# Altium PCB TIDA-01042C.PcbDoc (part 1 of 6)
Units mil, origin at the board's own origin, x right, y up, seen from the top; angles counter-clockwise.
Board outline 8300 x 7100 mil, 8 copper layers (Top Layer, Signal Layer 1, Signal Layer 2, Signal Layer 3, Signal Layer 4, Signal Layer 5, Signal Layer 6, Bottom Layer), stack 59.2 mil thick; 551 components, 303 nets, 1611 pads, 2322 vias.
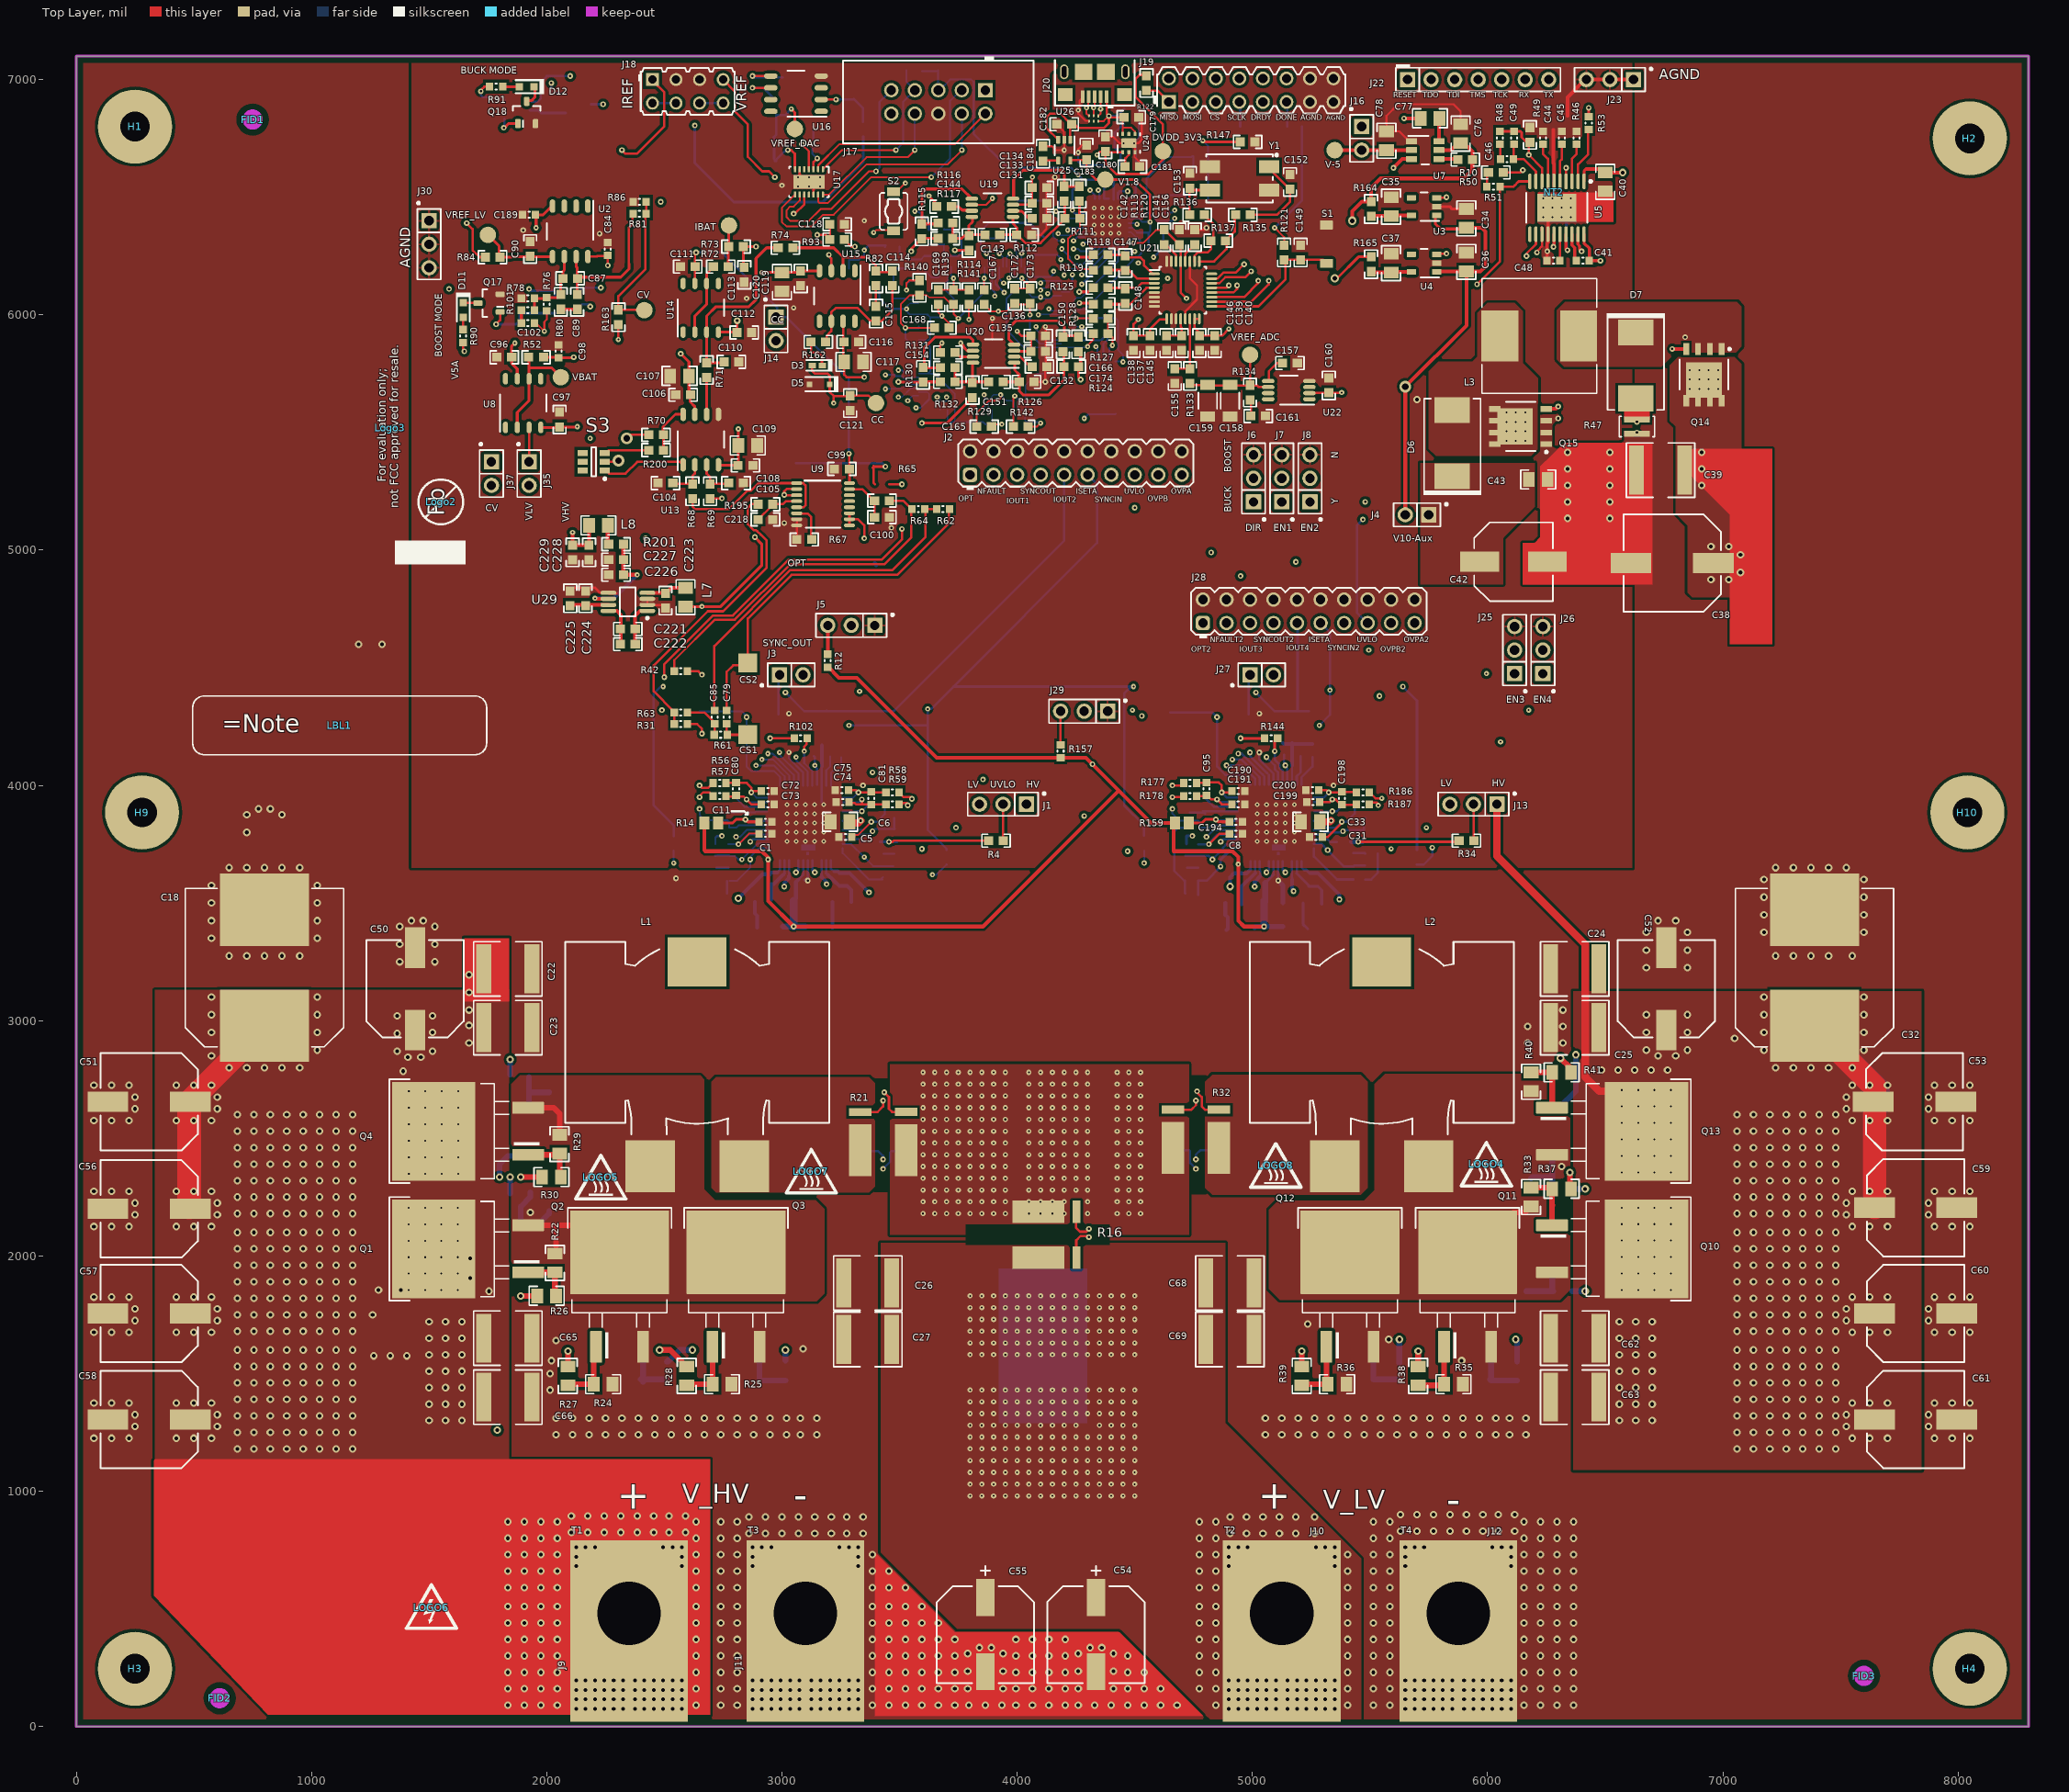
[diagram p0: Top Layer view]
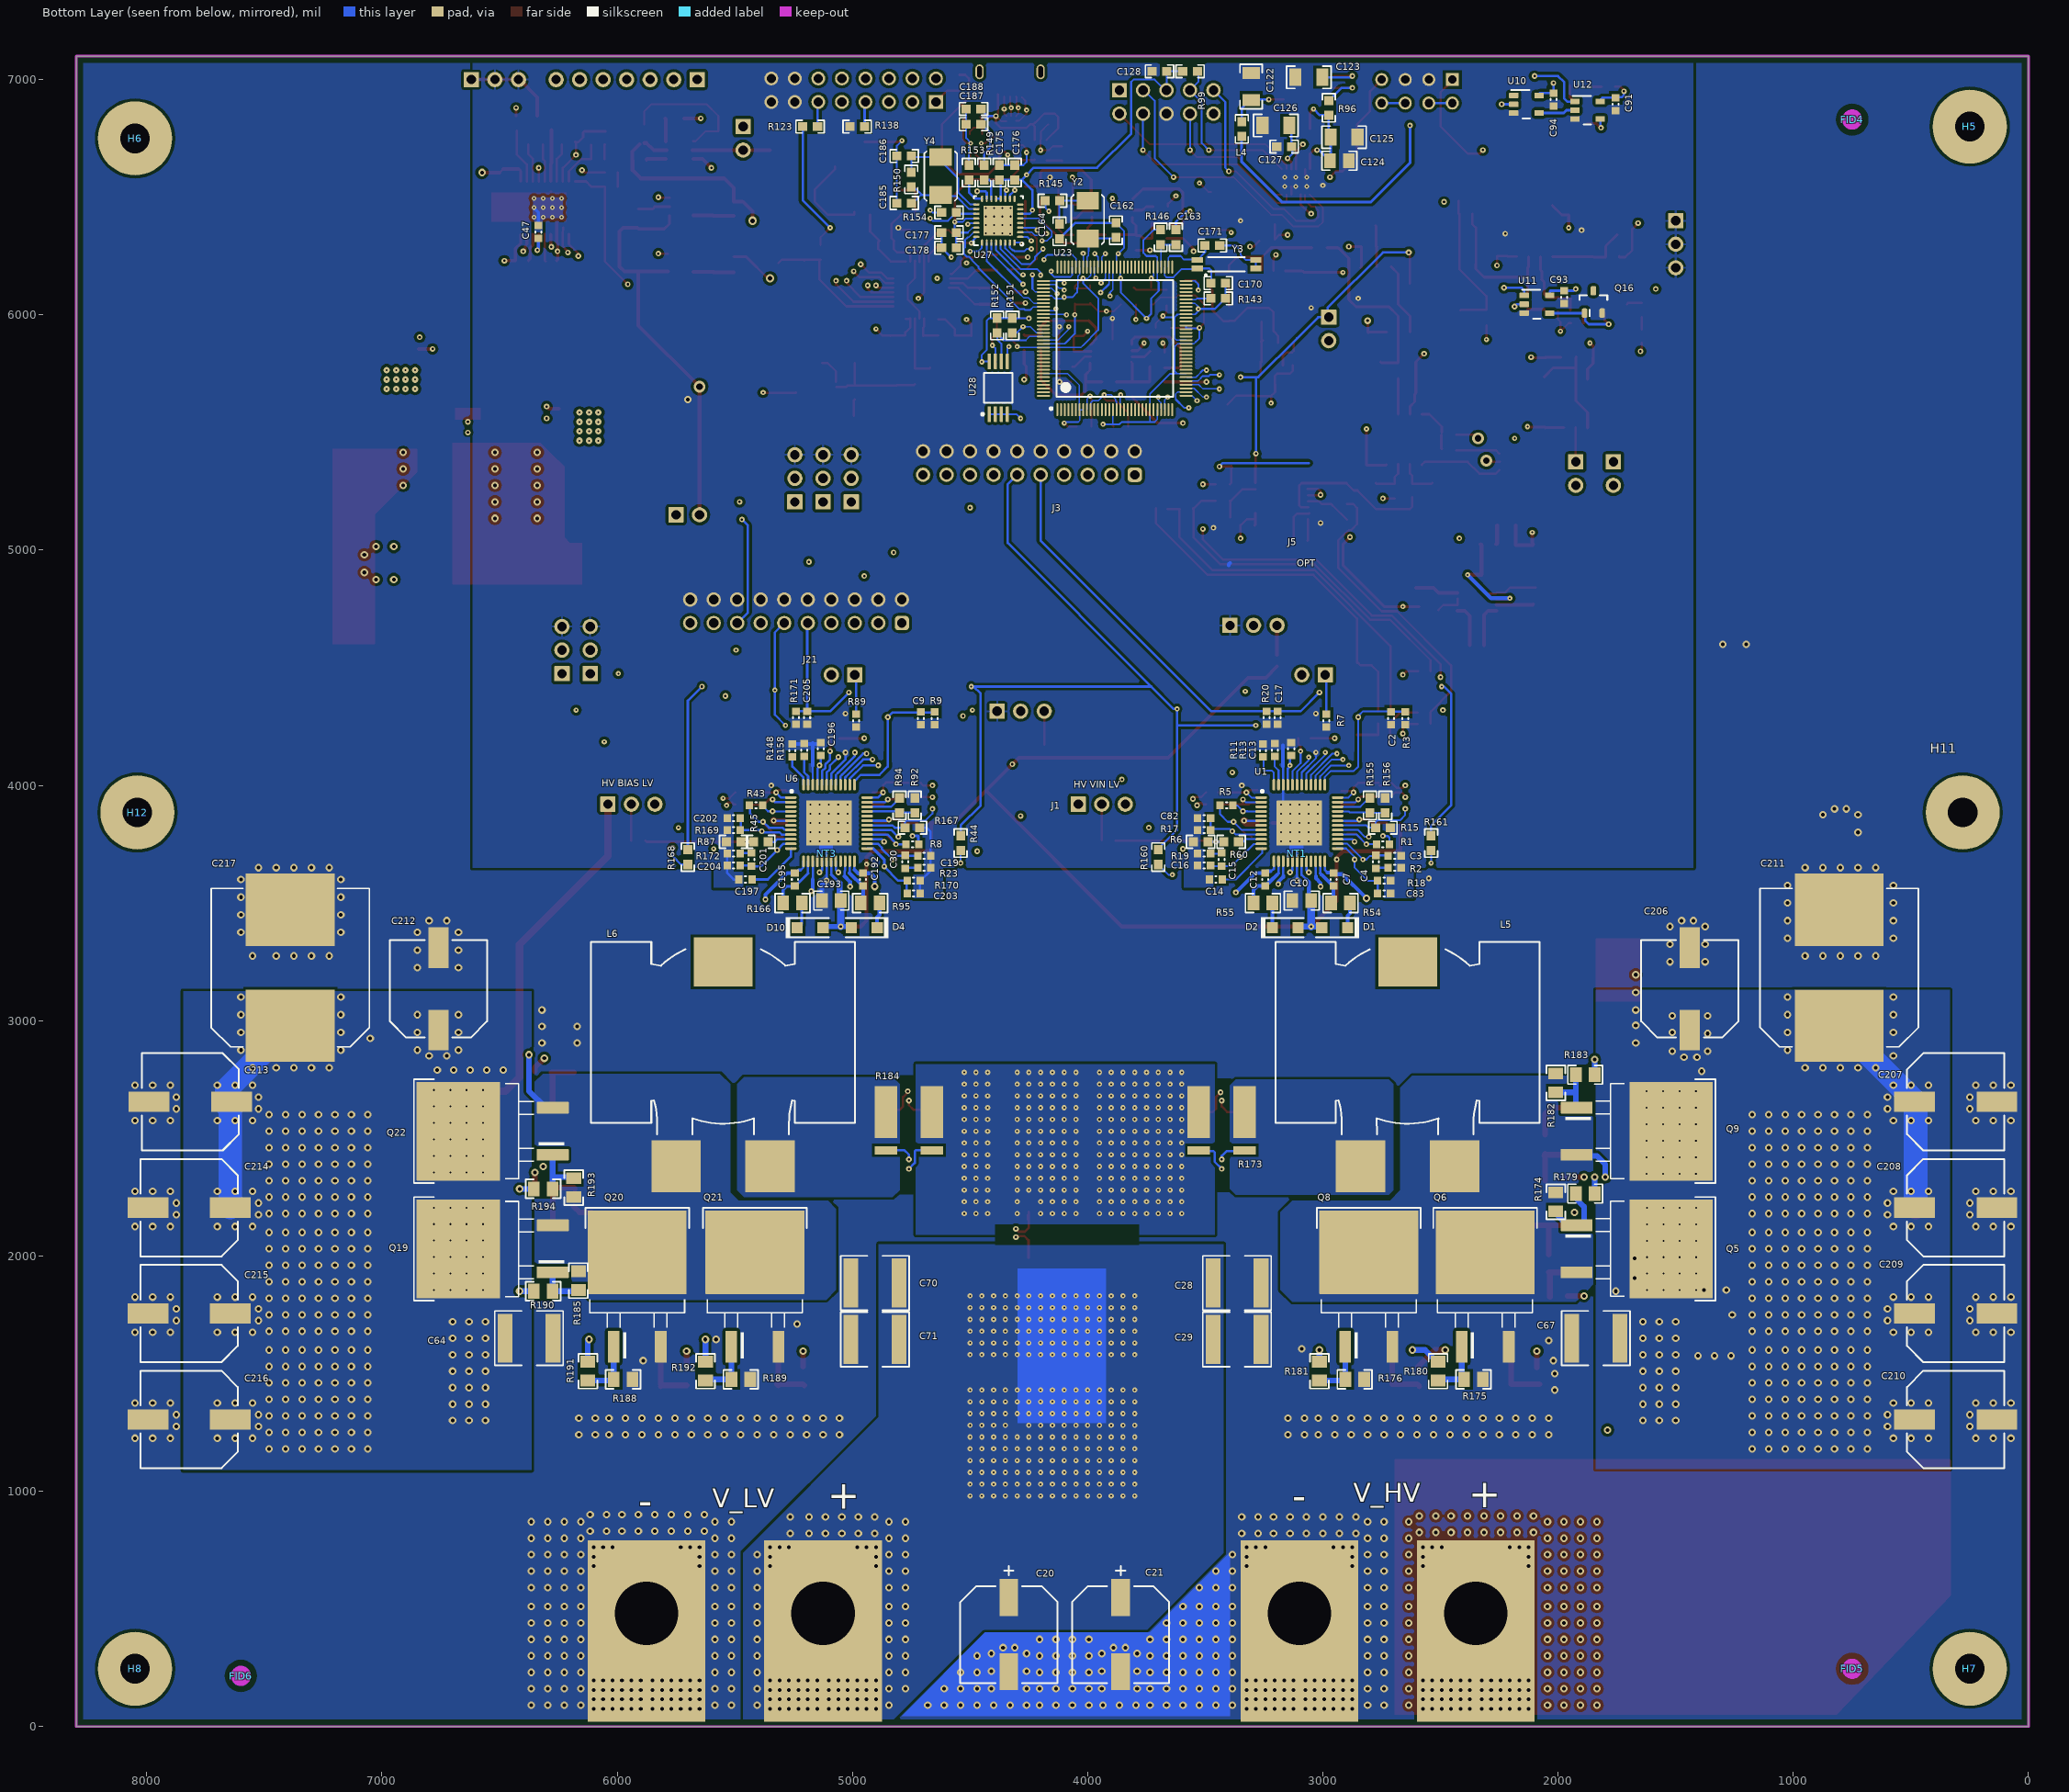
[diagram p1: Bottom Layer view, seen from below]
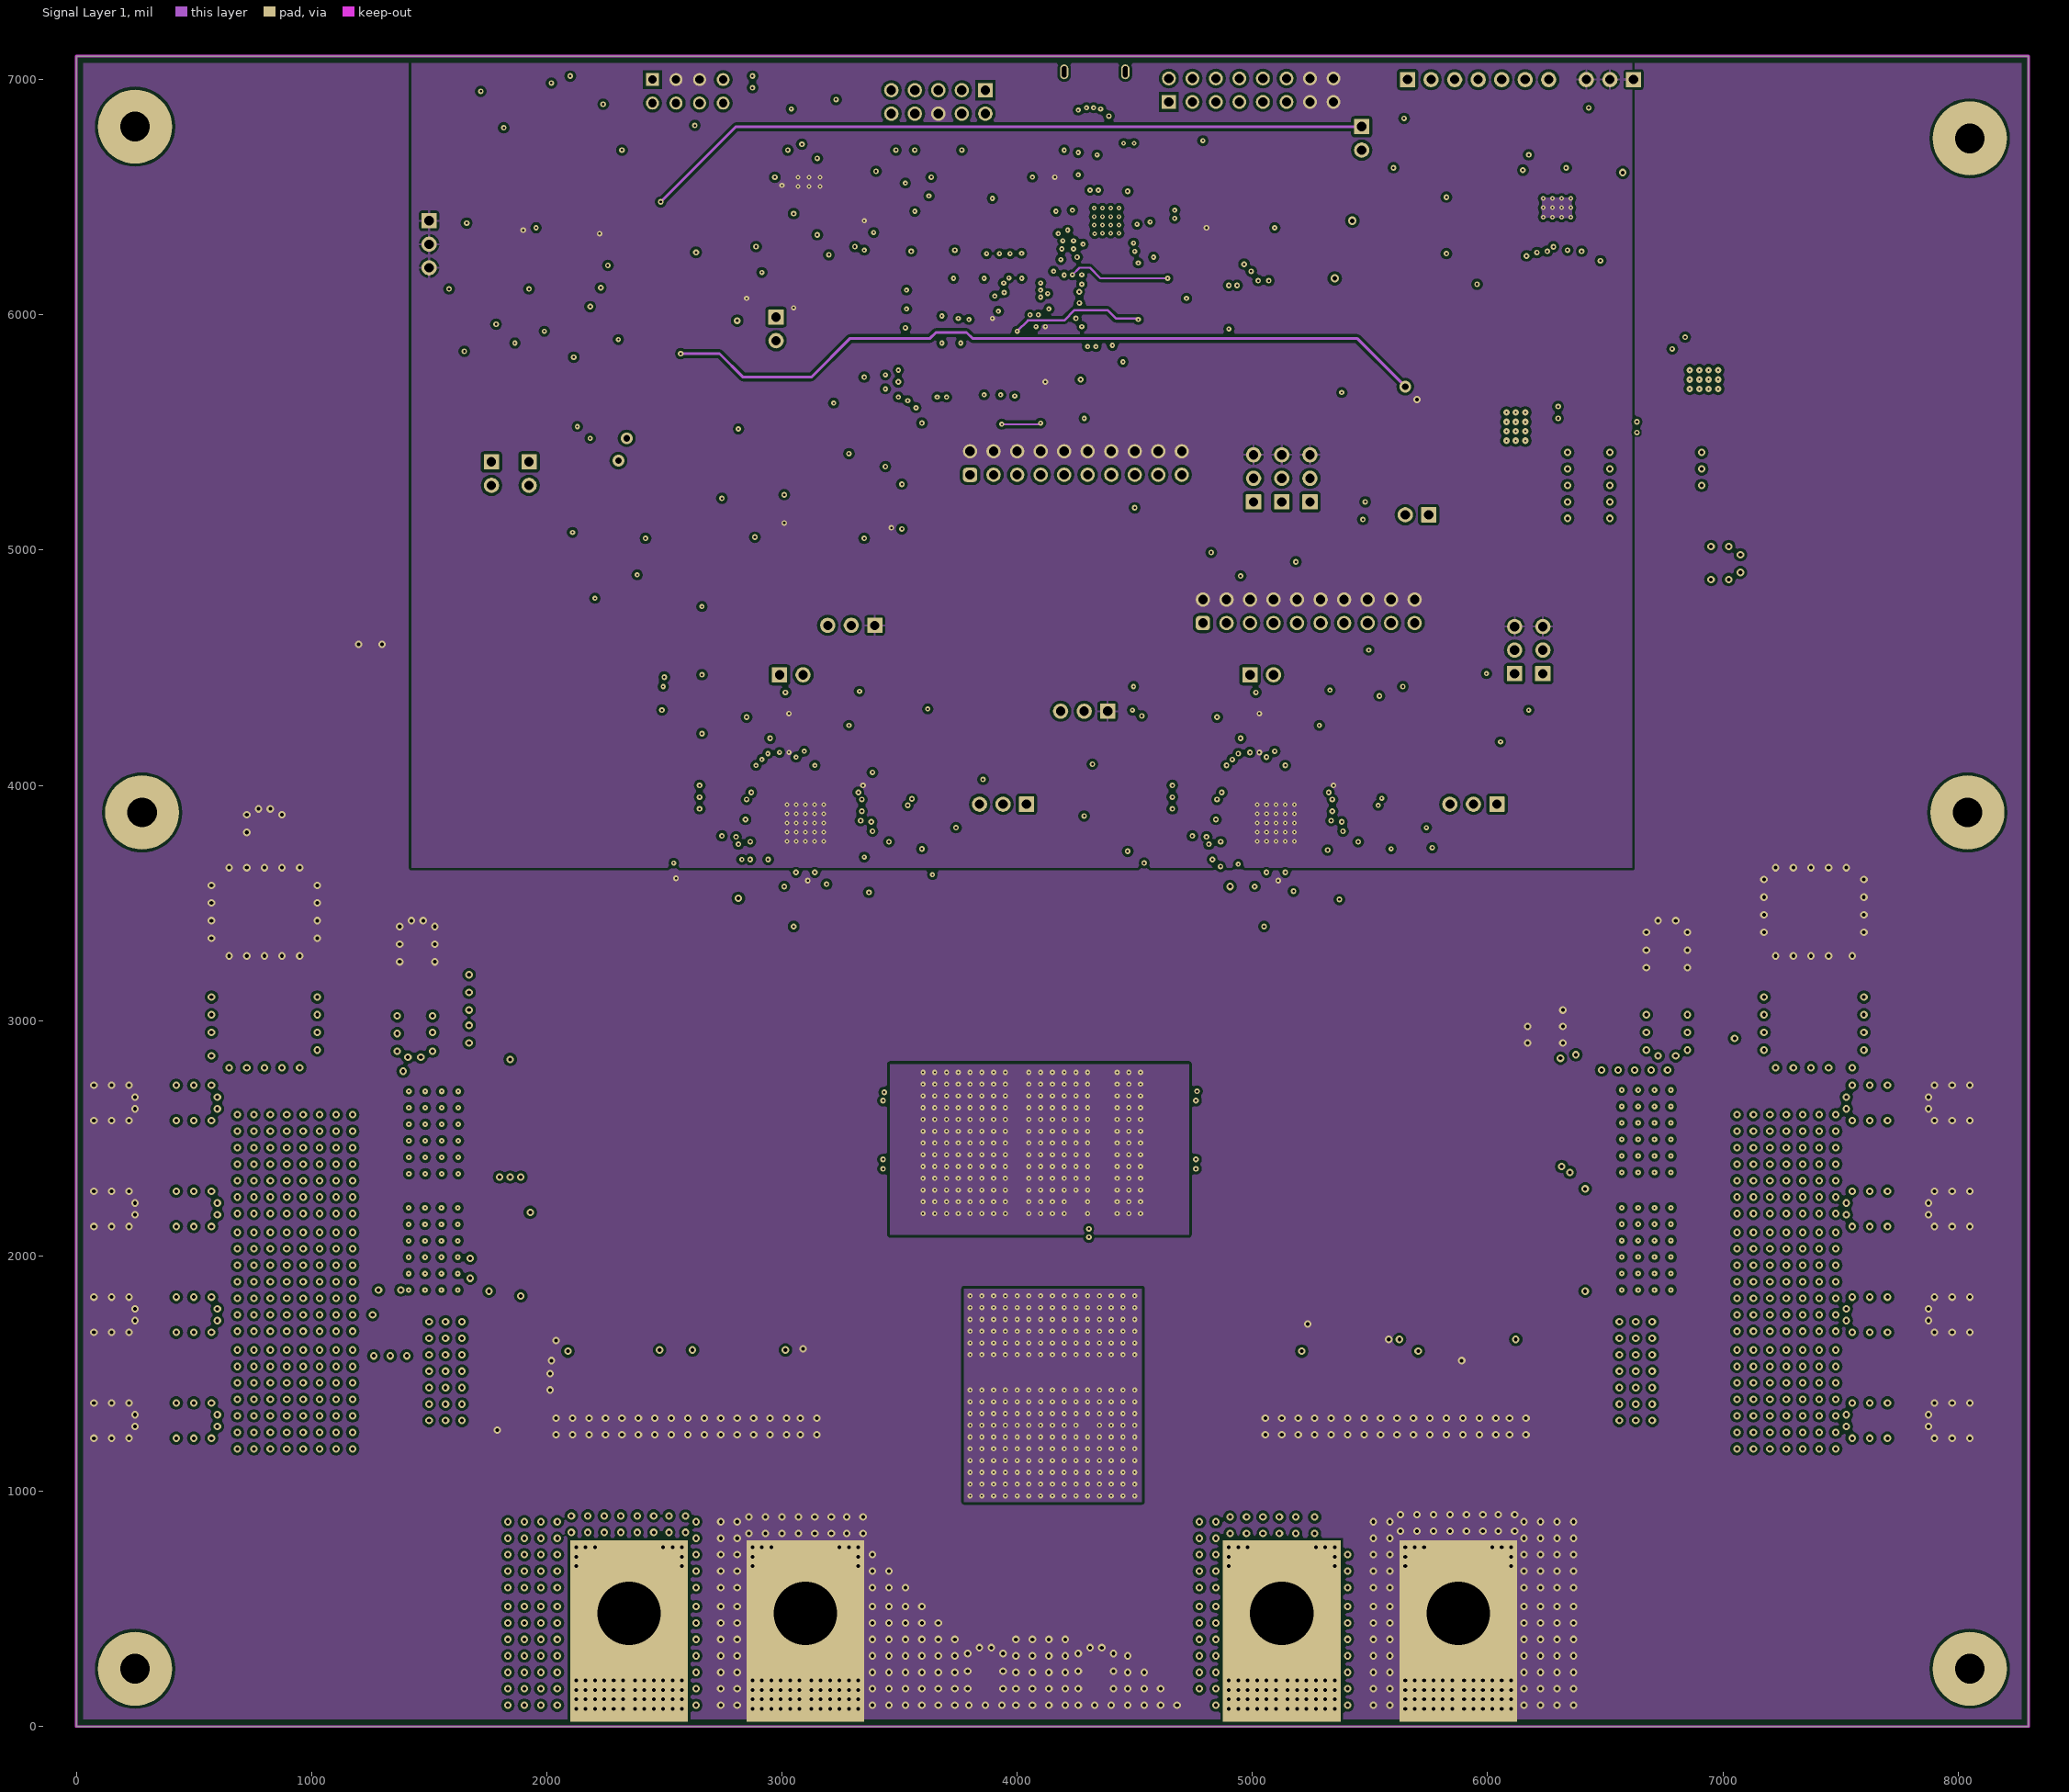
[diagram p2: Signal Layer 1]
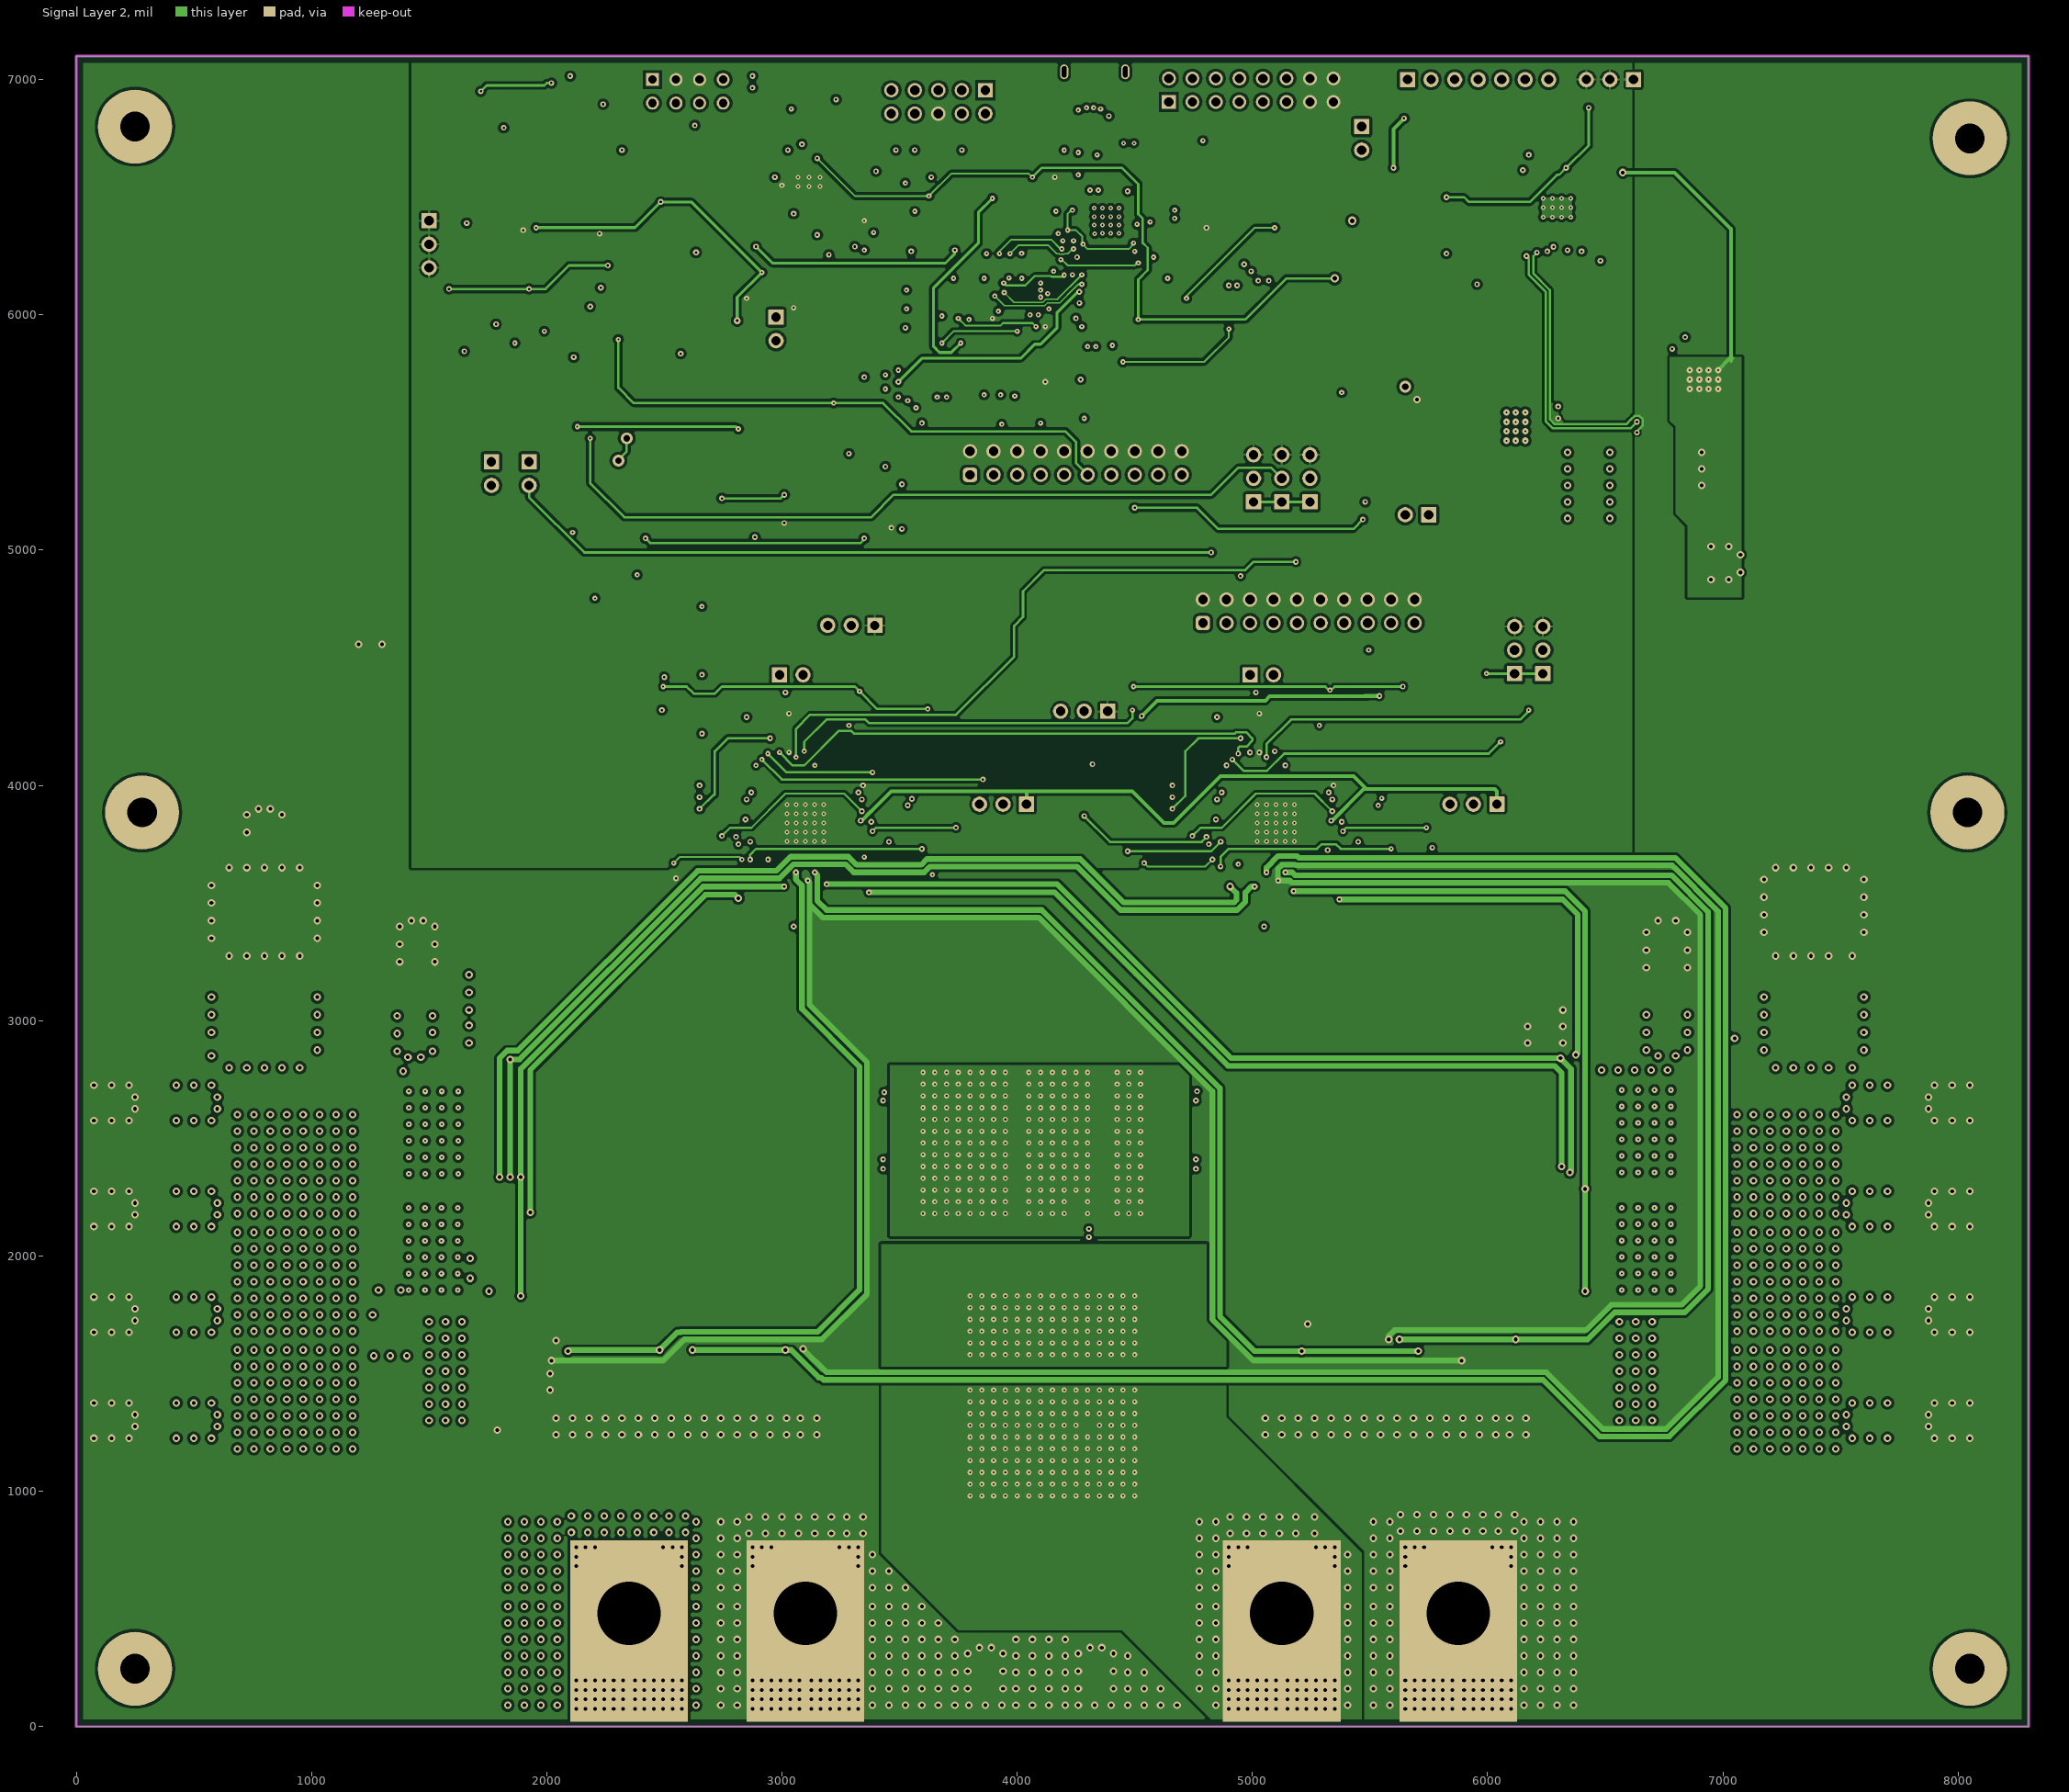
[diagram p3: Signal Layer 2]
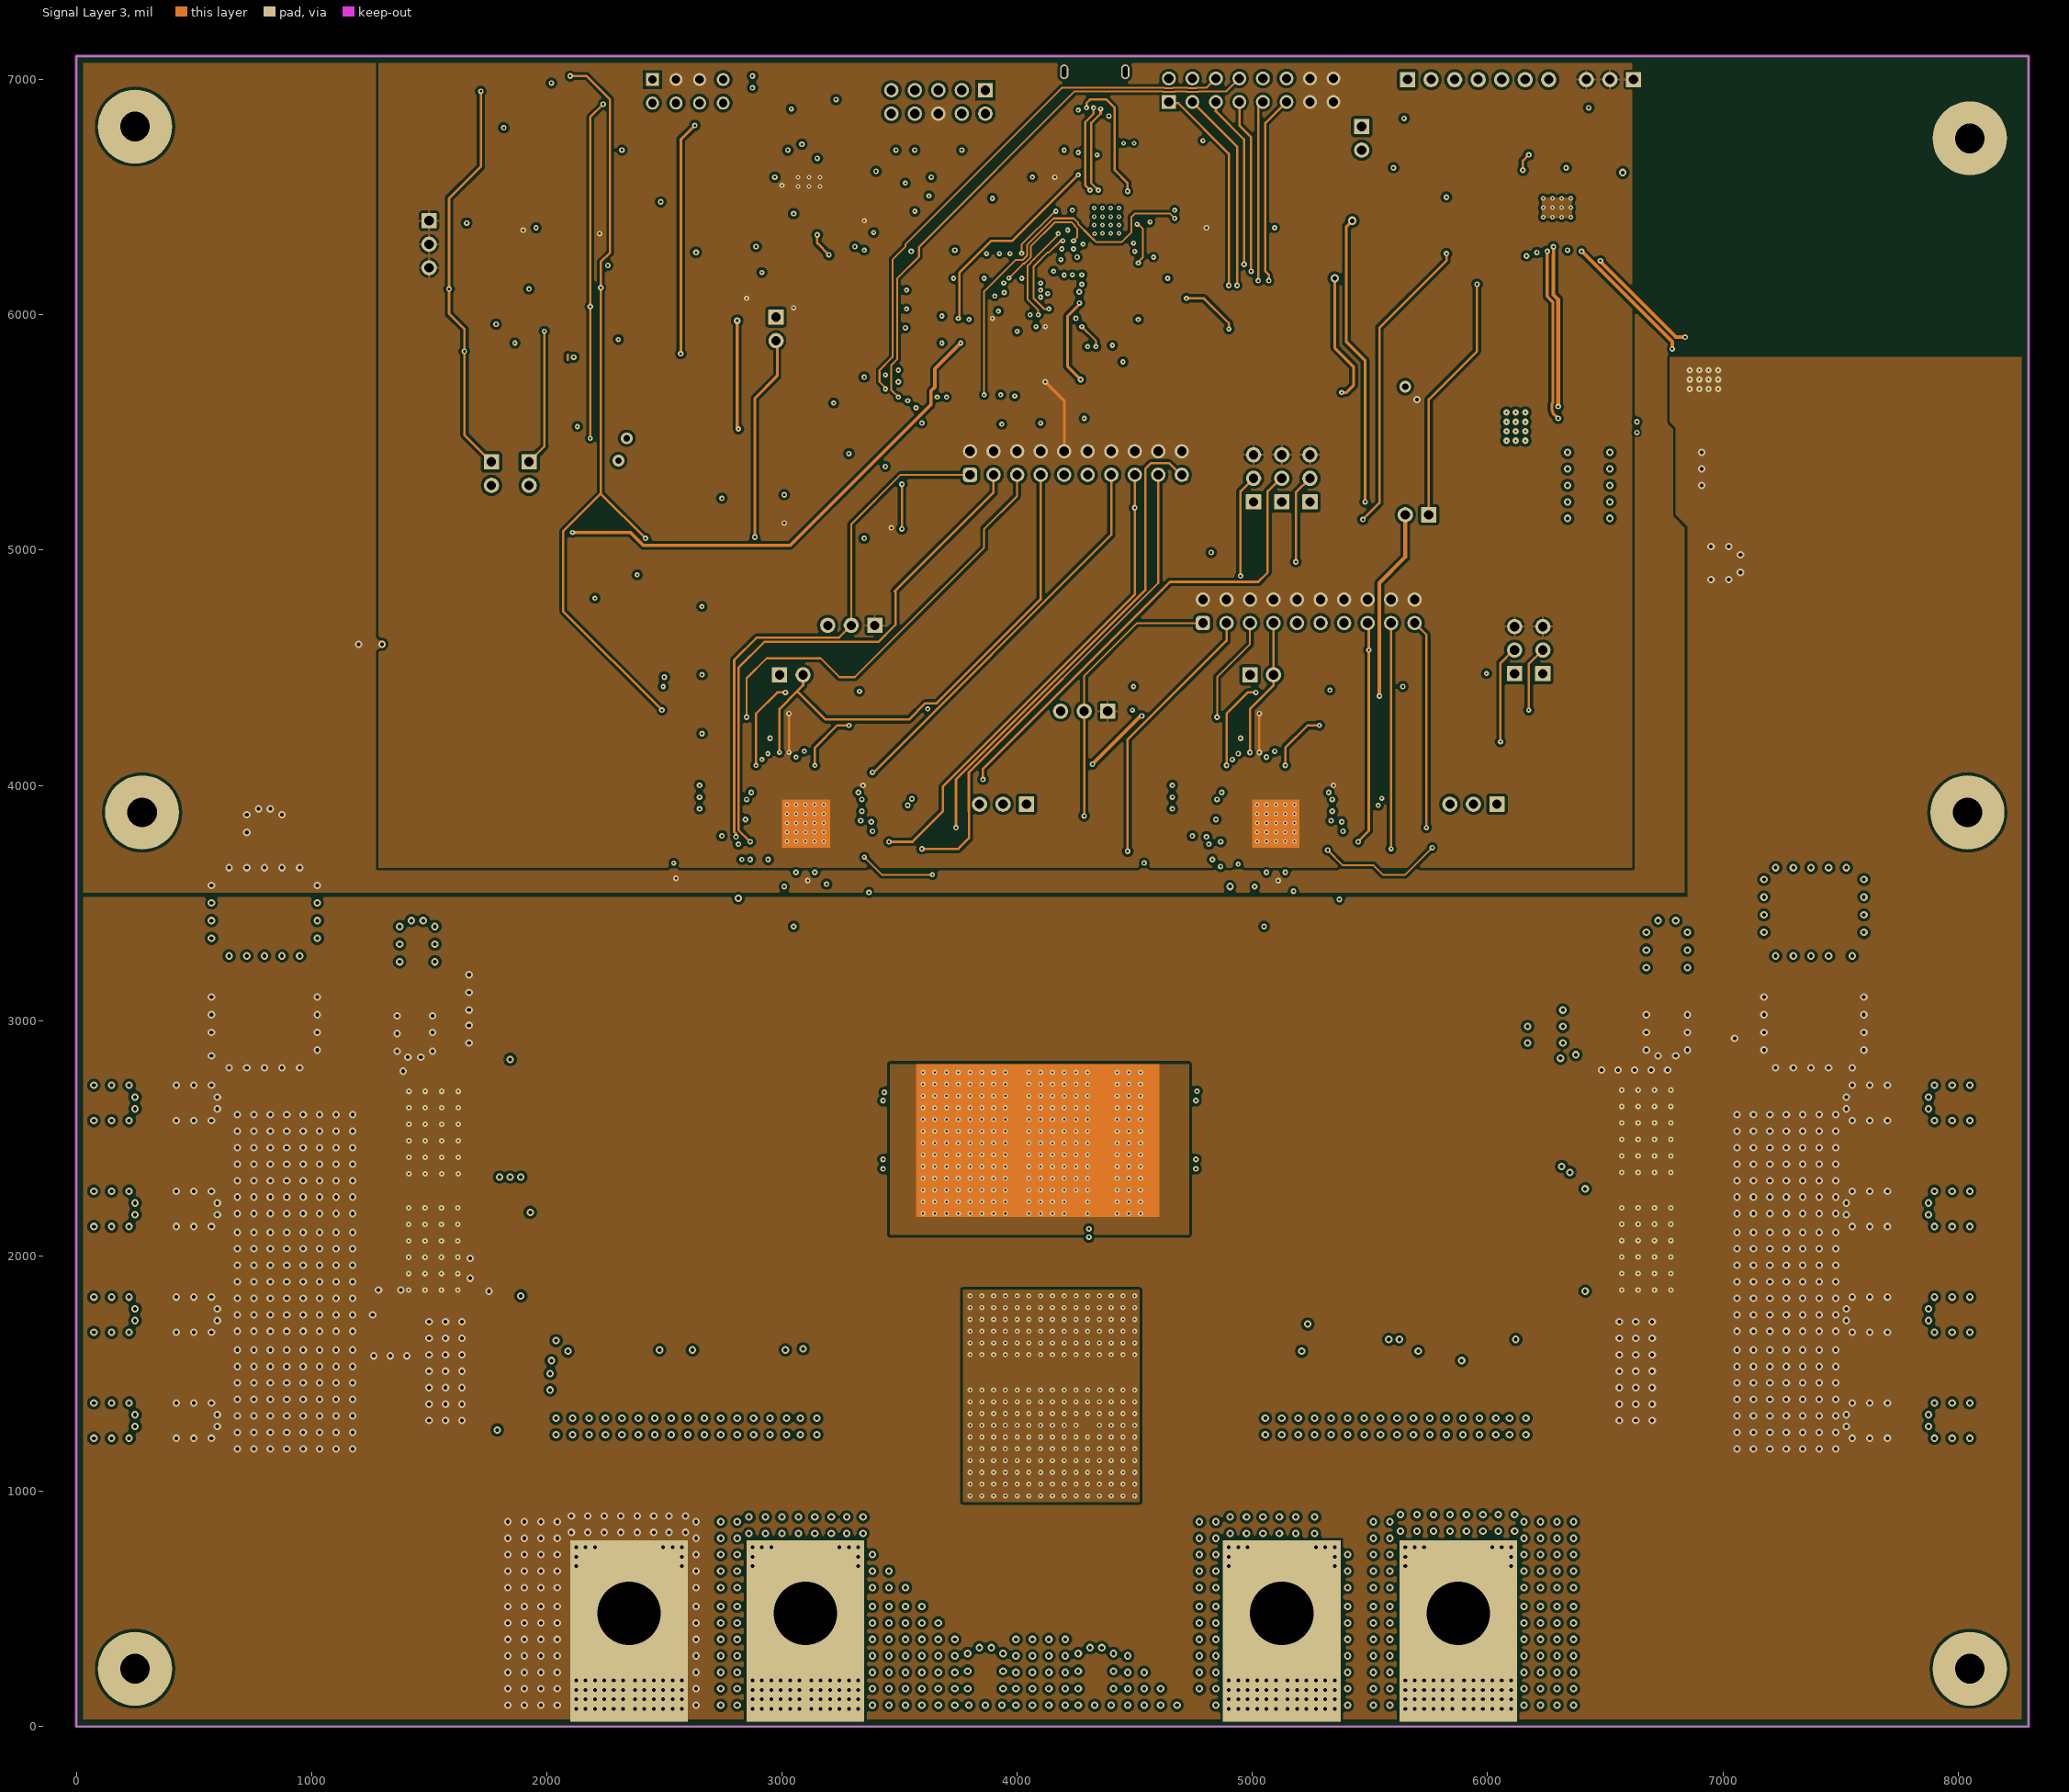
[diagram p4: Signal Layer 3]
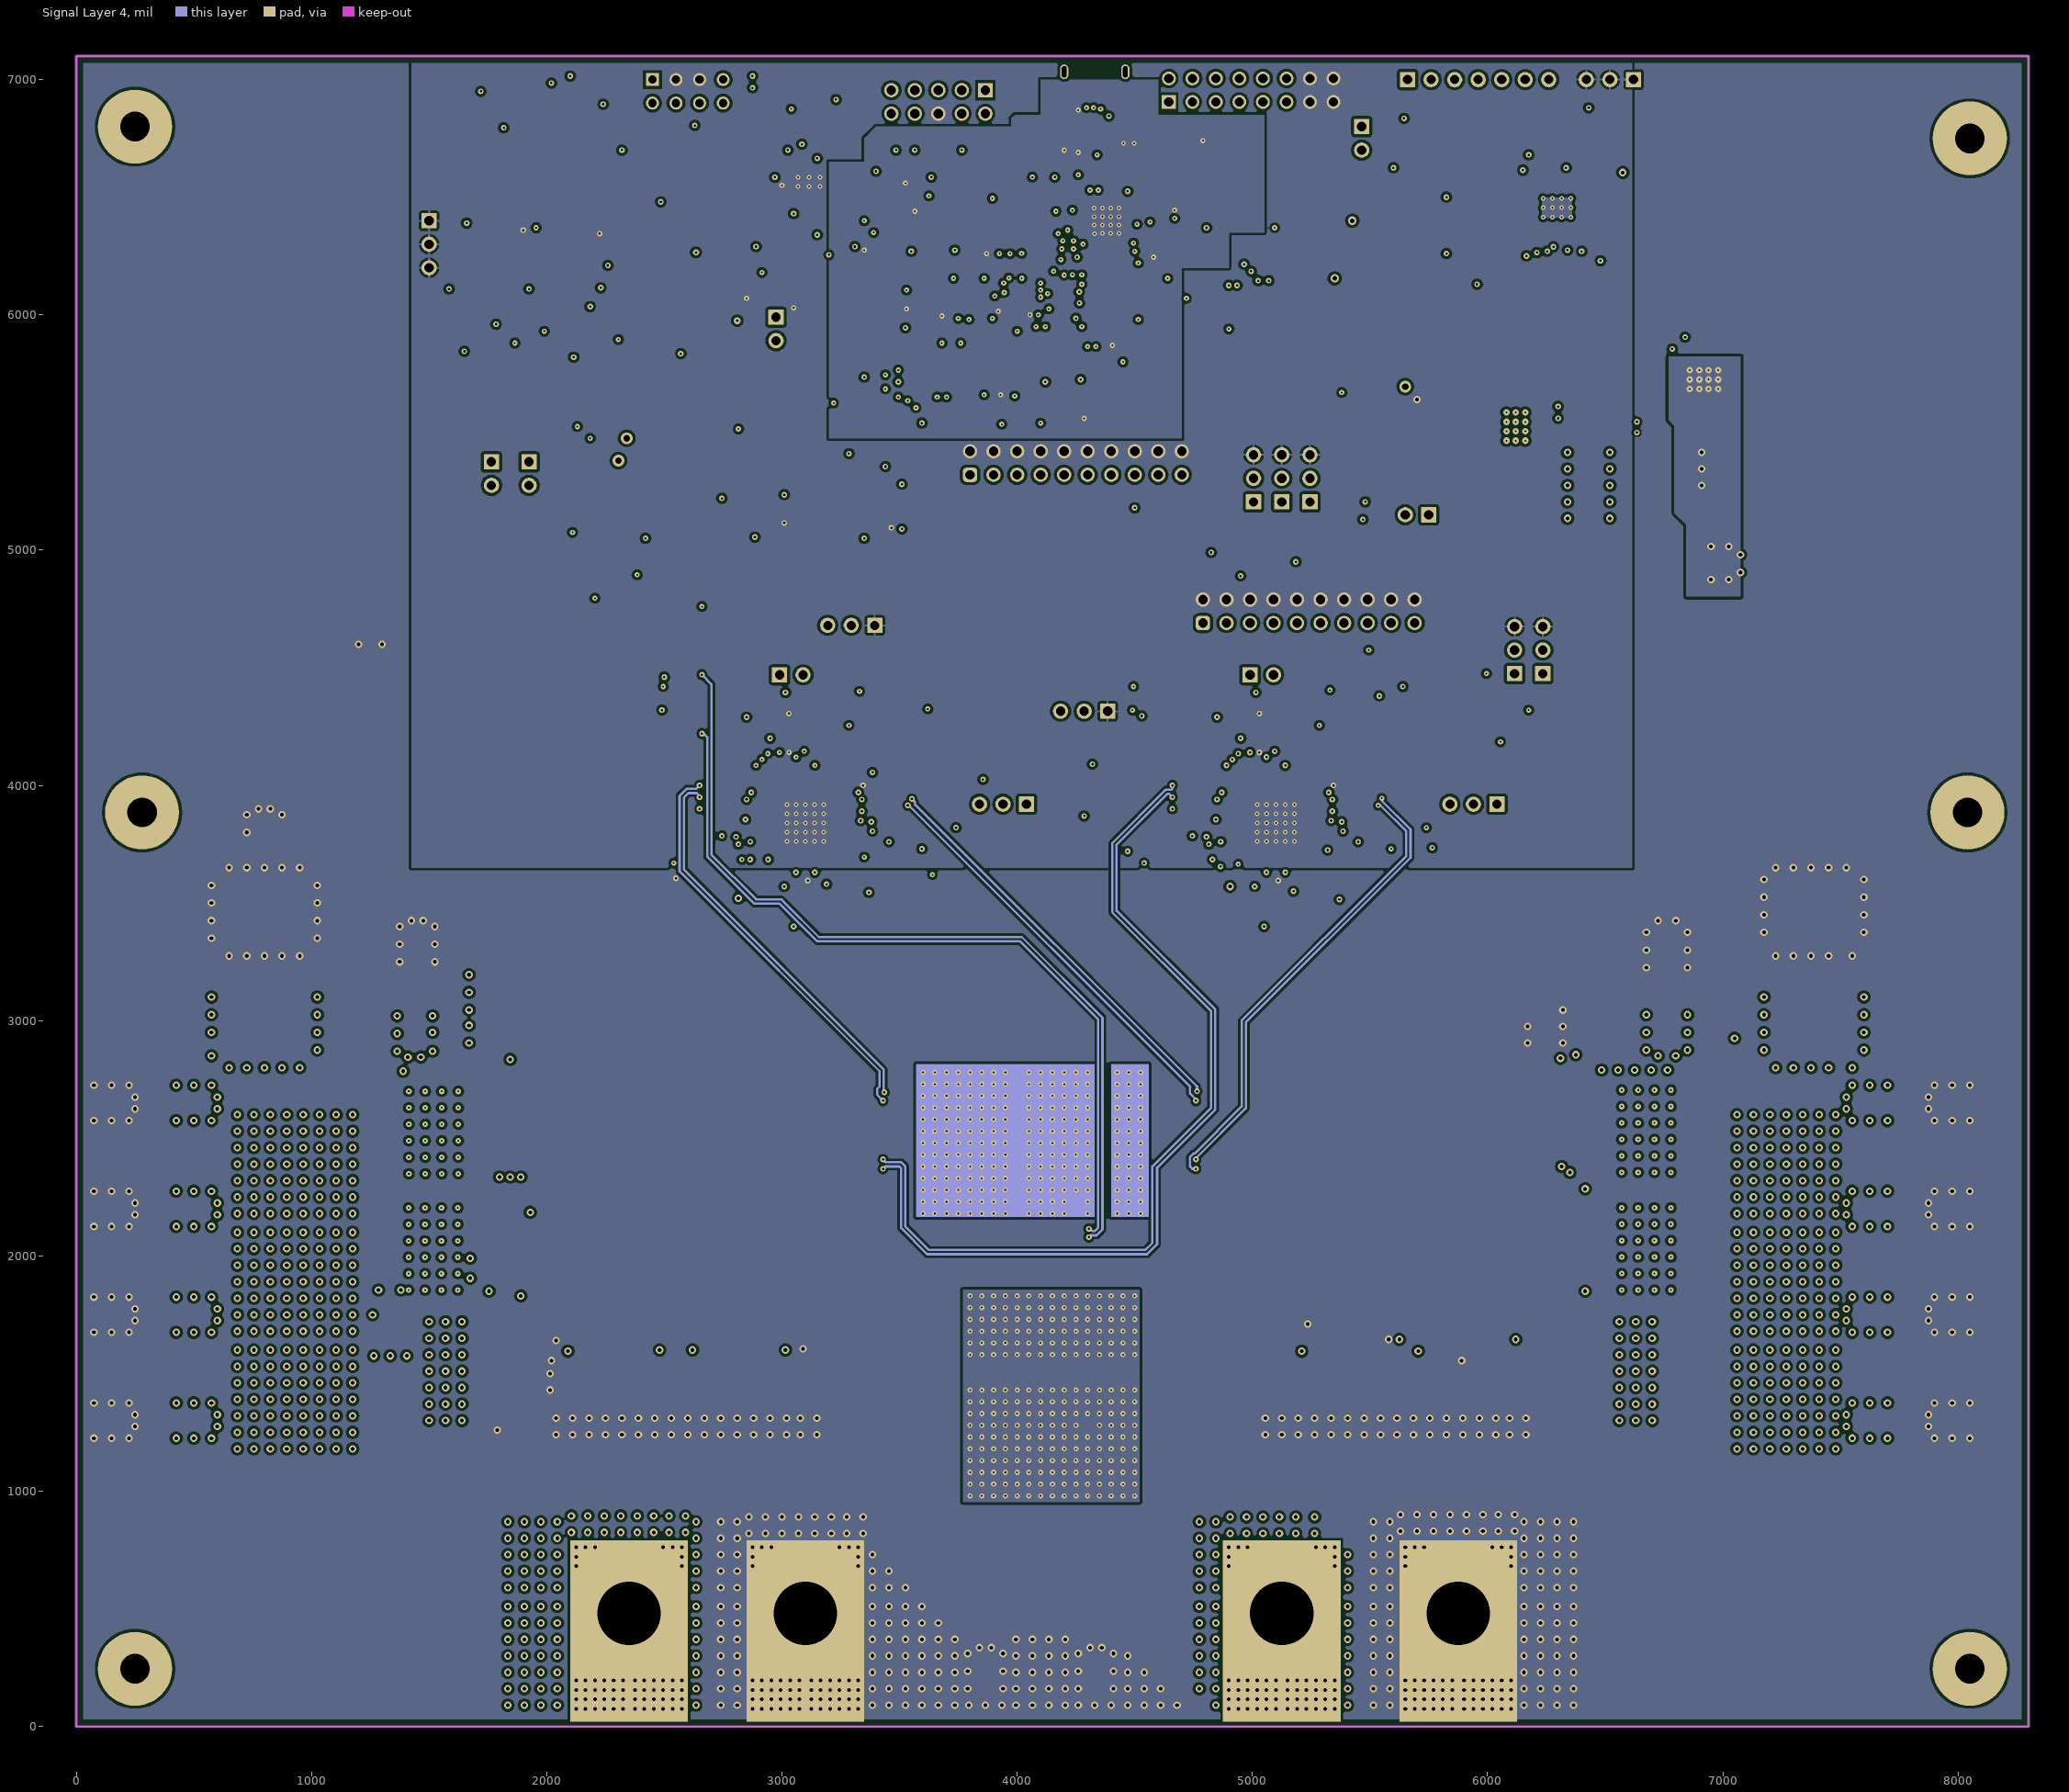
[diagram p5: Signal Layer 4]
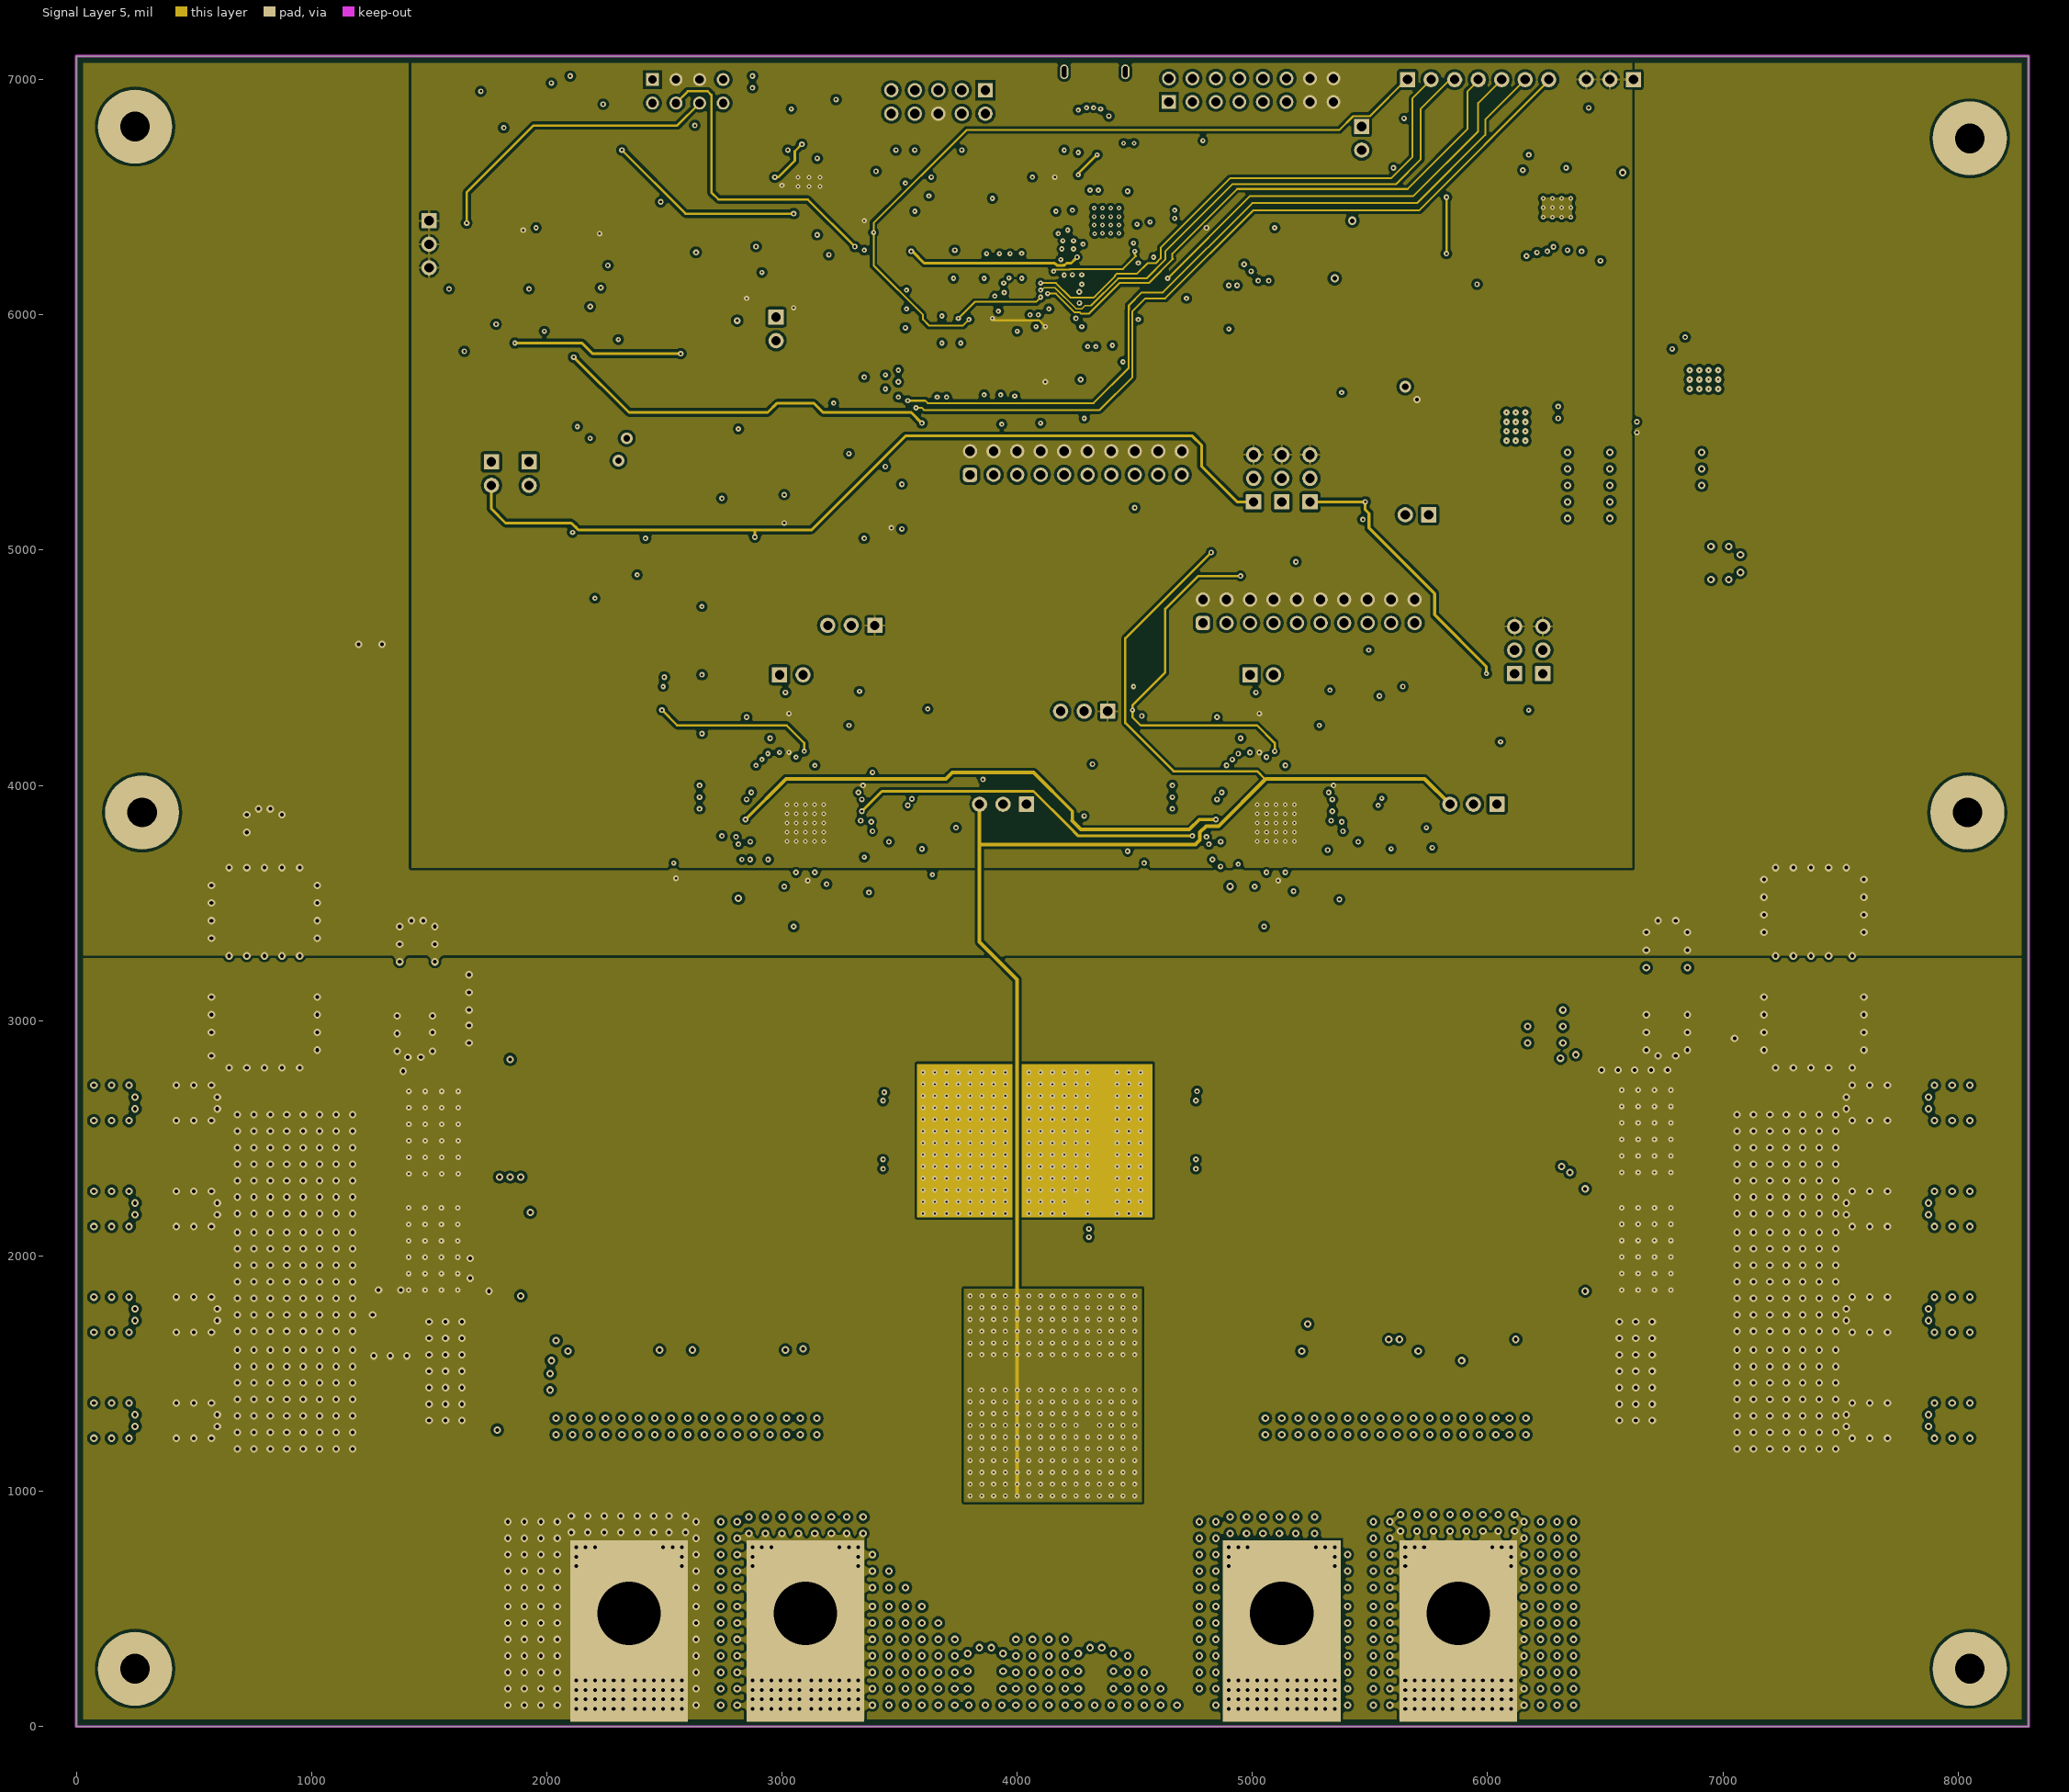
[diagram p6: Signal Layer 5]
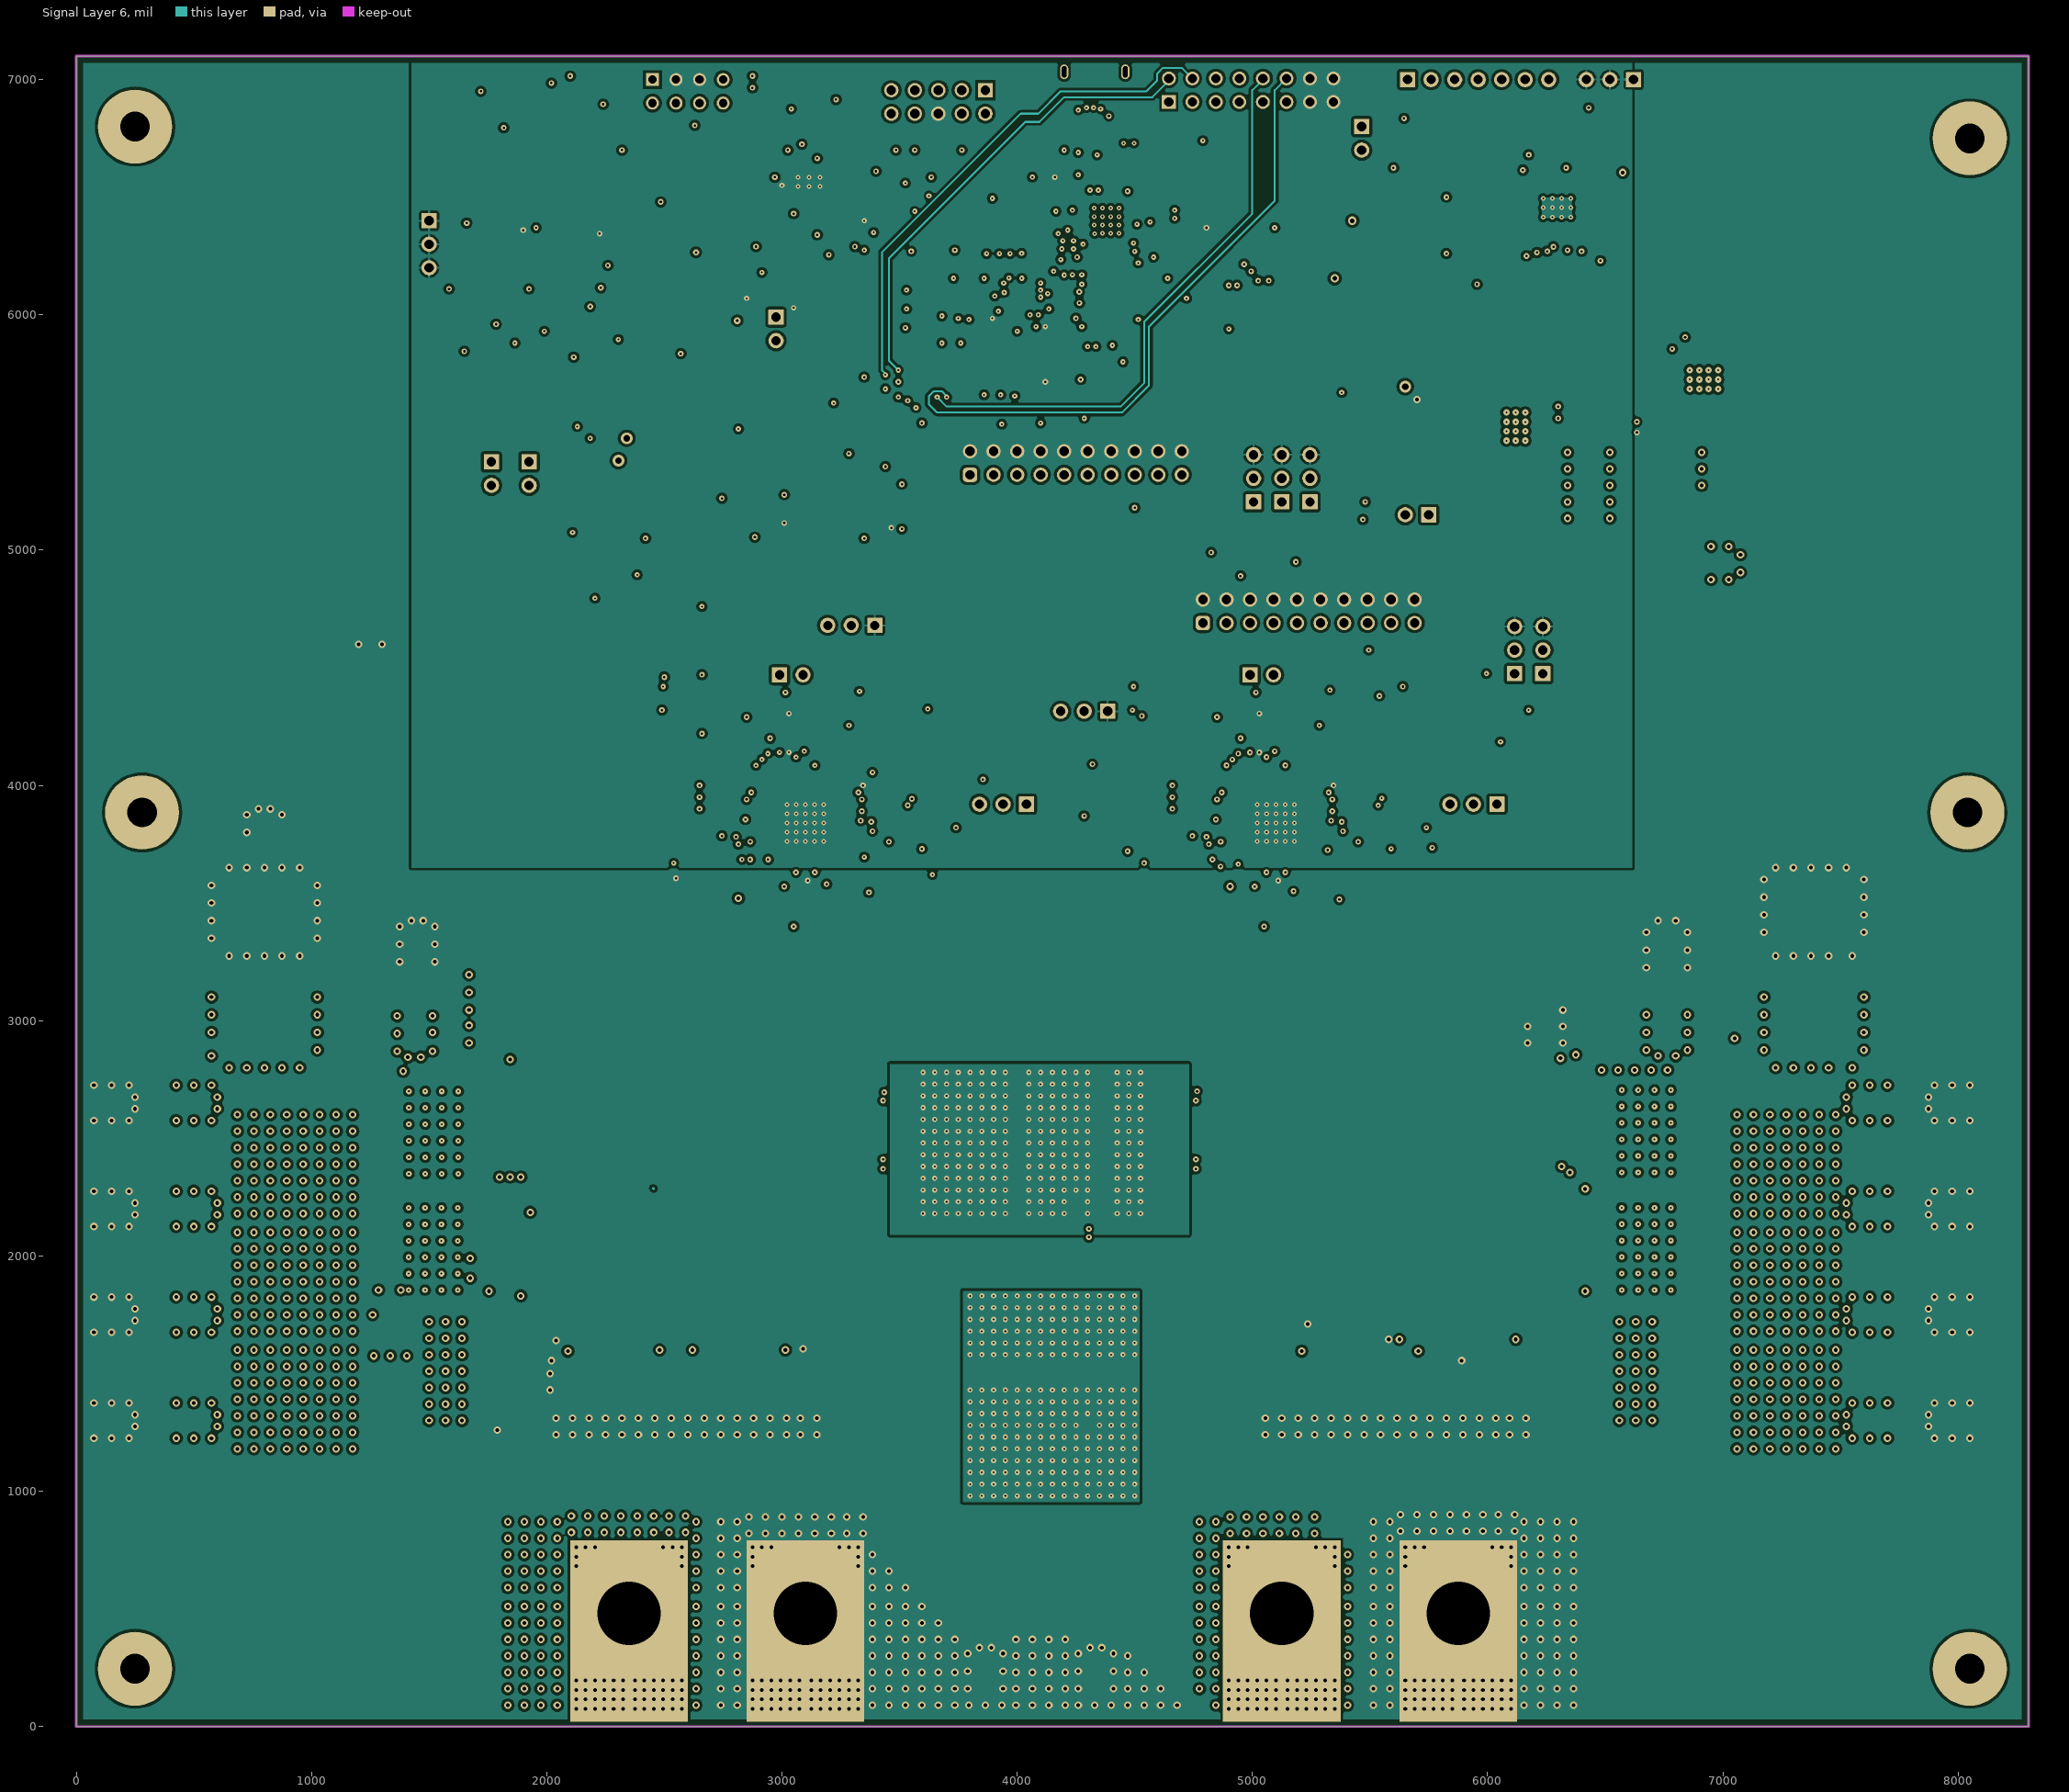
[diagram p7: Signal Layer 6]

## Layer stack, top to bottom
Top Solder: solder mask 0.4, Solder Resist, Dk 3.5
Top Layer: signal copper 3.2
Dielectric1: core 5, FR-4, Dk 4.8
Signal Layer 1: signal copper 2.8
Dielectric 2: prepreg 5, FR-4, Dk 4.2
Signal Layer 2: signal copper 2.8
Dielectric 3: core 5, FR-4, Dk 4.2
Signal Layer 3: signal copper 2.8
Dielectric4: prepreg 6, FR-4, Dk 4.2
Signal Layer 4: signal copper 2.8
Dielectric 5: core 5, FR-4, Dk 4.2
Signal Layer 5: signal copper 2.8
Dielectric 6: prepreg 5, FR-4, Dk 4.2
Signal Layer 6: signal copper 2.8
Dielectric 7: core 5, FR-4, Dk 4.2
Bottom Layer: signal copper 3.2
Bottom Solder: solder mask 0.4, Solder Resist, Dk 3.5

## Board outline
0,0 0,7100 8300,7100 8300,0

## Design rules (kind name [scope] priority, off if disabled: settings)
AcuteAngle [All] p1: minimum=3.30000000000000E+0001 checktracksonly=FALSE
AssemblyTestPointUsage [All] p1: valid=2
Clearance Clearance_USB [InComponent('J20') vs OnLayer('Keep-Out Layer')] p1: gap=30 ignorepadtopadclearanceinfootprint=FALSE
Clearance Clearance_Lugs2BoardEdge [HasFootprint('Panduit_CXS70-14-C') vs IsKeepOut] p2: gap=0 ignorepadtopadclearanceinfootprint=FALSE
Clearance Clearance_Keepouts [((IsTrack Or IsArc) And Not InPoly) And IsFree and IsKeepOut vs ((IsTrack Or IsArc) And Not InPoly) And IsFree and IsKeepOut] p3: gap=0 ignorepadtopadclearanceinfootprint=FALSE
Clearance Clearance_BoardEdge_MountingHoles [OnCopper and InComponentClass('Mounting Holes') vs IsKeepOut] p4: gap=40 ignorepadtopadclearanceinfootprint=FALSE except(0: Arc-Hole Track-Hole SMDPad-Hole THPad-Hole Via-Hole Fill-Hole Poly-Hole Region-Hole Text-Hole)
Clearance Clearance_BoardEdge_Poly [OnCopper and InPoly vs IsKeepOut] p5: gap=25 ignorepadtopadclearanceinfootprint=FALSE except(0: Arc-Hole Track-Hole SMDPad-Hole THPad-Hole Via-Hole Fill-Hole Poly-Hole Region-Hole Text-Hole)
Clearance Clearance_BoardEdge [OnCopper and Not InComponentClass('Logo') and not InComponentClass('FiducialMark') and not InRegion(1000,500,4000,800) and Not IsKeepout vs IsKeepOut] p6: gap=40 ignorepadtopadclearanceinfootprint=FALSE
Clearance Clearance_Poly [InPolygon] p7: gap=11.9 ignorepadtopadclearanceinfootprint=FALSE except(0: Arc-Hole Track-Hole SMDPad-Hole THPad-Hole Via-Hole Fill-Hole Poly-Hole Region-Hole Text-Hole)
Clearance [All] p8: gap=7.87 ignorepadtopadclearanceinfootprint=FALSE except(0: Arc-Hole Track-Hole SMDPad-Hole THPad-Hole Via-Hole Fill-Hole Poly-Hole Region-Hole Text-Hole)
ComponentClearance ComponentClearance_NetTie1 [HasFootprint('PHP0048D_L') vs HasFootprint('Net-Tie_10mil')] p1: gap=0 collisioncheckmode=3 verticalgap=0 showdistances=FALSE
ComponentClearance ComponentClearance_NetTie2 [HasFootprint('MXA20A_N') vs HasFootprint('Net-Tie_10mil')] p2: gap=0 collisioncheckmode=3 verticalgap=0 showdistances=FALSE
ComponentClearance ComponentClearance_Lugs2Banana [HasFootprint('Panduit_CXS70-14-C') vs HasFootprint('Johnson_108-0740-001')] p3: gap=0 collisioncheckmode=3 verticalgap=0 showdistances=FALSE
ComponentClearance ComponentClearance_MountingHoles_FiducialMarks [InComponentClass('Mounting Holes') vs InComponentClass('FiducialMark')] p4: gap=50 collisioncheckmode=3 verticalgap=10 showdistances=FALSE
ComponentClearance ComponentClearance_Shunt [InComponentClass('Header') vs InComponentClass('Shunt')] p5: gap=0 collisioncheckmode=3 verticalgap=0 showdistances=FALSE
ComponentClearance ComponentClearance_Logo [InComponentClass('Logo')] p6: gap=50 collisioncheckmode=3 verticalgap=10 showdistances=FALSE
ComponentClearance ComponentClearance_ScrewToNut [(HasFootprint('NY PMS 440 0025 PH')) vs HasFootprint('KEYSTONE_2205')] p7: gap=0 collisioncheckmode=3 verticalgap=0 showdistances=FALSE
ComponentClearance ComponentClearance_MountingHoles [InComponentClass('Mounting Holes')] p8: gap=100 collisioncheckmode=3 verticalgap=100000 showdistances=FALSE
ComponentClearance ComponentClearance_SmallPassives [HasFootprint('0201*') or HasFootprint('0402*') or HasFootprint('0508') or HasFootprint('0603*') or HasFootprint('0612') or HasFootprint('0805*') or HasFootprint('0815*') or HasFootprint('0830*') or HasFootprint('1206*') or HasFootprint('1210*') or HasFootprint('1808*') or HasFootprint('1812*') or HasFootprint('1825*') or HasFootprint('2010*') or HasFootprint('2220*') or HasFootprint('2225*') or HasFootprint('2512*') or HasFootprint('2728*') or HasFootprint('3518*') vs HasFootprint('0201*') or HasFootprint('0402*') or HasFootprint('0508') or HasFootprint('0603*') or HasFootprint('0612') or HasFootprint('0805*') or HasFootprint('0815*') or HasFootprint('0830*') or HasFootprint('1206*') or HasFootprint('1210*') or HasFootprint('1808*') or HasFootprint('1812*') or HasFootprint('1825*') or HasFootprint('2010*') or HasFootprint('2220*') or HasFootprint('2225*') or HasFootprint('2512*') or HasFootprint('2728*') or HasFootprint('3518*')] p9: gap=10 collisioncheckmode=3 verticalgap=10 showdistances=FALSE
ComponentClearance ComponentClearance_THtoSMT [IsThruComponent vs IsSMTComponent] p10: gap=20 collisioncheckmode=3 verticalgap=30 showdistances=FALSE
ComponentClearance ComponentClearance_THtoTH [IsThruComponent vs IsThruComponent] p11: gap=20 collisioncheckmode=3 verticalgap=30 showdistances=FALSE
ComponentClearance [All] p12: gap=30 collisioncheckmode=3 verticalgap=10 showdistances=FALSE
DiffPairsRouting [All] p1: maxlimit=100 minlimit=10 mostfreqgap=10 toplayer_minwidth=15 toplayer_maxwidth=15 toplayer_prefwidth=15 midlayer1_minwidth=15 midlayer1_maxwidth=15 midlayer1_prefwidth=15 midlayer2_minwidth=15 midlayer2_maxwidth=15 midlayer2_prefwidth=15 midlayer3_minwidth=15 midlayer3_maxwidth=15 midlayer3_prefwidth=15 midlayer4_minwidth=15 midlayer4_maxwidth=15 midlayer4_prefwidth=15 midlayer5_minwidth=15 midlayer5_maxwidth=15 midlayer5_prefwidth=15 midlayer6_minwidth=15 midlayer6_maxwidth=15 midlayer6_prefwidth=15 bottomlayer_minwidth=15 bottomlayer_maxwidth=15 bottomlayer_prefwidth=15 maxuncoupledlength=1000
FabricationTestPointUsage TestPointUsage [All] p1: valid=2 allowmultiple=FALSE
FabricationTestpoint Testpoint [All] p1: side=3 testpointundercomponent=TRUE minsize=40 maxsize=100 preferedsize=60 minholesize=0 maxholesize=40 preferedholesize=32 testpointgrid=1 allowsidetop=TRUE allowsidebottom=TRUE usegrid=TRUE gridtolerance=0.01
FanoutControl Fanout_LCC [IsLCC] p1: bgadir=Out bgaviamode=Centered fanoutstyle=Auto fanoutdirection=Alternating viagrid=1 // Fanout_LCC (Default Rule)
FanoutControl Fanout_BGA [IsBGA] p2: bgadir=Out bgaviamode=Centered fanoutstyle=Auto fanoutdirection=Alternating viagrid=1 // Fanout_BGA (Default Rule)
FanoutControl Fanout_Default [All] p4: bgadir=Out bgaviamode=Centered fanoutstyle=Auto fanoutdirection=Alternating viagrid=1 // Fanout_Default (Default Rule)
FanoutControl Fanout_Small [(CompPinCount < 5)] p5: bgadir=Out bgaviamode=Centered fanoutstyle=Auto fanoutdirection=OutThenIn viagrid=1 // Fanout_Small (Default Rule)
Height [All] p1: minheight=0 maxheight=1010 prefheight=500
HoleSize [All] p1: absolutevalues=TRUE maxlimit=500 minlimit=7.87 maxpercent=80.000 minpercent=20.000
HoleToHoleClearance I/OHoleClearance [HasFootprint('Johnson_108-0740-001') vs HasFootprint('Panduit_CXS70-14-C')] p1: gap=0 allowstackedmicrovias=TRUE
HoleToHoleClearance [All] p2: gap=10 allowstackedmicrovias=TRUE
MinimumAnnularRing MinimumAnnularRing_ThermalPadVias [IsVia and InAnyComponent] p1: minimumring=5.84
MinimumAnnularRing [All] p2: minimumring=7
MinimumSolderMaskSliver MinimumSolderMaskSliver_Logo [InComponentClass('Logo') vs InComponentClass('Logo')] p1: minsoldermaskwidth=0.7
MinimumSolderMaskSliver [All] p2: minsoldermaskwidth=1.9
PlaneConnect [All] p1: planeconnectstyle=Relief reliefexpansion=10 reliefentries=4 reliefconductorwidth=10 reliefairgap=10
PolygonConnect PolygonConnect_AGND [InNet('AGND') vs (HasFootprint('SAMTEC_HMTSW-130-07-G-D-240') OR HasFootprint('Samtec_HTSW-102-07-G-S') OR HasFootprint('Samtec_HTSW-103-07-G-S'))] p1: connectstyle=Relief reliefconductorwidth=10 reliefentries=4 polygonreliefangle="90 Angle" airgapwidth=10
PolygonConnect [All] p2: connectstyle=Direct reliefconductorwidth=10 reliefentries=4 polygonreliefangle="90 Angle" airgapwidth=10
RoutingVias ThermalPadVias [IsVia and InAnyComponent] p1: holewidth=7.87 width=19.68 viastyle="Through Hole" minholewidth=7.87 minwidth=19.68 maxholewidth=16 maxwidth=32
RoutingVias [All] p2: holewidth=16 width=32 viastyle="Through Hole" minholewidth=7.87 minwidth=20 maxholewidth=40 maxwidth=65
SilkToBoardRegionClearance [NOT ((IsComment OR IsDesignator) AND (Hide <> 'FAIL'))AND NOT InRegion (100,-500,8000,1500)] p1:
SilkToSilkClearance SilkToSilkClearance_Pb-FreeLogo [(HasFootprint('Pb-Free_Overlay_Medium') OR HasFootprint('Pb-Free_Overlay_Small')) vs (HasFootprint('Pb-Free_Overlay_Medium') OR HasFootprint('Pb-Free_Overlay_Small'))] p1: silktosilkclearance=0
SilkToSilkClearance [All] p2: silktosilkclearance=5
SilkToSolderMaskClearance "Silk to Solder Mask Opening" [All] p1: minsilkscreentomaskgap=1 clearancetoexposedcopper=FALSE
SolderMaskExpansion [All] p1: expansion=1.97
Width [All] p1: maxlimit=100 minlimit=6 preferedwidth=10 checkconnectedcopper=TRUE
13 further rules are at their usual default settings.

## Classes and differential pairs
component class "SV601272A-Current-Control REV3": C99 C100 C104 C105 C106 C107 C108 C109 C110 C111 C112 C113 C114 C115 C116 C117 C118 C119 C120 C121 C218 CC D3 D5 IBAT J14 J30 R65 R67 R68 R69 R70 R71 R72 R73 R74 R82 R93 R162 R195 R200 S3 U9 U13 U14 U15
component class SV601272A-Bias: C34 C35 C36 C37 C38 C39 C40 C41 C42 C43 C44 C45 C46 C47 C48 C49 C76 C77 C78 C221 C222 C223 C224 C225 C226 C227 C228 C229 D6 D7 J4 J16 J23 L3 L7 L8 NT2 Q14 Q15 R10 R46 R47 R48 R49 R50 R51 R53 R164 R165 R201 U3 U4 U5 U7 U29 V-5
component class SV601272A-Power: C18 C20 C21 C22 C23 C24 C25 C26 C27 C28 C29 C32 C50 C51 C52 C53 C54 C55 C56 C57 C58 C59 C60 C61 C62 C63 C64 C65 C66 C67 C68 C69 C70 C71 C79 C85 CS1 CS2 J9 J10 J11 J12 L1 L2 Q1 Q2 Q3 Q4 Q10 Q11 Q12 Q13 R16 R21 R22 R24 R25 R26 R27 R28 R29 R30 R31 R32 R33 R35 R36 R37 R38 R39 R40 R41 R42 R56 R57 R58 R59 R61 R62 R63 R64 T1 T2 T3 T4
component class SV601272A-Controller1: C1 C2 C3 C4 C5 C6 C7 C10 C11 C12 C13 C14 C15 C16 C17 C72 C73 C74 C75 C80 C81 C82 C83 D1 D2 J1 J2 J3 J5 J6 J7 J8 NT1 R1 R2 R3 R4 R5 R6 R7 R11 R12 R13 R14 R15 R17 R18 R19 R20 R54 R55 R60 R102 R155 R156 R160 R161 U1
component class "Mounting Holes": H1 H2 H3 H4 H9 H10
component class Label: LBL1
component class FiducialMark: FID1 FID2 FID3 FID4 FID5 FID6
component class SV601272A-HW: FID1 FID2 FID3 FID4 FID5 FID6 H1 H2 H3 H4 H5 H6 H7 H8 H9 H10 H11 H12 LBL1 Logo2 Logo3 LOGO4 LOGO5 LOGO6 LOGO7 LOGO8 ZZ1 ZZ2 ZZ3 ZZ4
component class AssemblyNote: ZZ1 ZZ2 ZZ3 ZZ4
component class Header: J1 J2 J3 J4 J5 J6 J7 J8 J13 J14 J16 J18 J19 J22 J23 J25 J26 J27 J28 J29 J30 J35 J37
component class SV601272A-Analog: C84 C87 C89 C90 C91 C93 C94 C96 C97 C98 C102 C189 CV D11 D12 J35 J37 Q16 Q17 Q18 R52 R76 R78 R80 R81 R84 R86 R90 R91 R101 R163 U2 U8 U10 U11 U12 VBAT VREF VREF_LV
component class SV601272A-DAC: C122 C123 C124 C125 C126 C127 C128 J17 J18 L4 R96 R99 U16 U17 VREF_DAC
component class SV601272A-ADC: C131 C132 C133 C134 C135 C136 C137 C138 C139 C140 C141 C142 C143 C144 C145 C146 C147 C148 C149 C150 C151 C152 C153 C154 C155 C156 C157 C158 C159 C160 C161 J19 R111 R112 R113 R114 R115 R116 R117 R118 R119 R120 R121 R122 R123 R124 R125 R126 R127 R128 R129 R130 R131 R132 R133 R134 R135 R136 R137 R138 S1 U19 U20 U21 U22 VREF_ADC Y1
component class SV601272A-TM4C_Main: C162 C163 C164 C165 C166 C167 C168 C169 C170 C171 C172 C173 C174 J22 R139 R140 R141 R142 R143 R145 R146 S2 U23 Y2 Y3
component class SV601272A-TM4C_Power: C175 C176 C177 C178 C179 C180 C181 C182 C183 C184 C185 C186 C187 C188 DVDD_3V3 J20 R147 R149 R150 R151 R152 R153 R154 U24 U25 U26 U27 U28 V1.8 Y4
component class ThermalPads: U24
component class "SV601272A-Power2 REV2": C206 C207 C208 C209 C210 C211 C212 C213 C214 C215 C216 C217 L5 L6 Q5 Q6 Q8 Q9 Q19 Q20 Q21 Q22 R173 R174 R175 R176 R177 R178 R179 R180 R181 R182 R183 R184 R185 R186 R187 R188 R189 R190 R191 R192 R193 R194
component class SV601272A-Controller2: C8 C9 C19 C30 C31 C33 C95 C190 C191 C192 C193 C194 C195 C196 C197 C198 C199 C200 C201 C202 C203 C204 C205 D4 D10 J13 J25 J26 J27 J28 J29 NT3 R8 R9 R23 R34 R43 R44 R45 R87 R89 R92 R94 R95 R144 R148 R157 R158 R159 R166 R167 R168 R169 R170 R171 R172 U6

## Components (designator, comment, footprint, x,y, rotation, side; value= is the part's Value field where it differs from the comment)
C1 "C1608C0G2A102J080AA" 0603L 2930,3795 r0 top value=1000pF
C2 "06031C103KAT2A" 0603L 2710,4285 r90 bottom value=0.01uF
C3 "C1608C0G2A102J080AA" 0603L 2695,3700 r0 bottom value=1000pF
C4 "GRM188R71E153KA01D" 0603L 2775,3675 r90 bottom value=0.015uF
C5 "C1608C0G2A102J080AA" 0603L 3270,3780 r180 top value=1000pF
C6 "C2012X7S2A105K125AB" 0805_HV 3247,3845 r180 top value=1uF
C7 "C1608X7R1H224K080AB" 0603L 2955,3600 r270 bottom value=0.22uF
C8 "C1608C0G2A102J080AA" 0603L 4930,3795 r0 top value=1000pF
C9 "06031C103KAT2A" 0603L 4710,4285 r90 bottom value=0.01uF
C10 "C2012X7R1C225K125AB" 0805_HV 3090,3510 r0 bottom value=2.2uF
C11 "GRM188R71E105KA12D" 0603L 2930,3845 r0 top value=1uF
C12 "C1608X7R1H224K080AB" 0603L 3245,3600 r90 bottom value=0.22uF
C13 "C0603C101J5GACTU" 0603L 3135,4155 r90 bottom value=100pF
C14 "06031C103KAT2A" 0603L 3455,3600 r0 bottom value=0.01uF
C15 "GRM188R71E153KA01D" 0603L 3430,3685 r90 bottom value=0.015uF
C16 "C1608C0G2A102J080AA" 0603L 3505,3660 r0 bottom value=1000pF
C17 "06031C103KAT2A" 0603L 3192.48,4287.52 r270 bottom value=0.01uF
C18 "EMVH101GDA101MLH0S" CAPSMT_62_LH0 800,3225 r90 top value=100uF
C19 "C1608C0G2A102J080AA" 0603L 4695,3700 r0 bottom value=1000pF
C20 "PCR1H181MCL1GS" CR_1000x1270 4335,390 r270 bottom value=180uF
C21 "PCR1H181MCL1GS" CR_1000x1270 3860,390 r270 bottom value=180uF
C22 "C5750X7R2A475M230KA" 2220_280 1835,3220 r0 top value=4.7uF
C23 "C5750X7R2A475M230KA" 2220_280 1835,2970 r0 top value=4.7uF
C24 "C5750X7R2A475M230KA" 2220_280 6370,3220 r180 top value=4.7uF
C25 "C5750X7R2A475M230KA" 2220_280 6370,2970 r180 top value=4.7uF
C26 "C5750X7R2A475M230KA" 2220_280 3365,1885 r180 top value=4.7uF
C27 "C5750X7R2A475M230KA" 2220_280 3365,1645 r180 top value=4.7uF
C28 "C5750X7R2A475M230KA" 2220_280 3365,1885 r180 bottom value=4.7uF
C29 "C5750X7R2A475M230KA" 2220_280 3365,1645 r180 bottom value=4.7uF
C30 "GRM188R71E153KA01D" 0603L 4775,3675 r90 bottom value=0.015uF
C31 "C1608C0G2A102J080AA" 0603L 5270,3780 r180 top value=1000pF
C32 "EMVH101GDA101MLH0S" CAPSMT_62_LH0 7390,3225 r90 top value=100uF
C33 "C2012X7S2A105K125AB" 0805_HV 5247,3845 r180 top value=1uF
C34 "C2012X7S2A105K125AB" 0805_HV 5910,6410 r90 top value=1uF
C35 "C2012X7S2A105K125AB" 0805_HV 5590,6460 r90 top value=1uF
C36 "C2012X7S2A105K125AB" 0805_HV 5910,6225 r90 top value=1uF
C37 "C2012X7S2A105K125AB" 0805_HV 5590,6220 r90 top value=1uF
C38 "EMVH101ADA220MJA0G" CAPSMT_62_JA0 6785,4945 r180 top value=22uF
C39 "C5750X7S2A106M230KB" 2220_250 6735,5340 r180 top value=10uF
C40 "C2012X7R2A104K125AA" 0805_HV 6500,6565 r270 top value=0.1uF
C41 "GRM188R72A104KA35D" 0603L 6405,6230 r180 top value=0.1uF
C42 "APXA160ARA181MHC0G" CAPSMT_62_HC0 6110,4950 r0 top value=180uF
C43 "C2012X7R1C225K125AB" 0805_HV 6215,5300 r0 top value=2.2uF
C44 "GRM188R72A104KA35D" 0603L 6235.31,6752.2 r90 top value=0.1uF
C45 "C1608C0G2A331J080AA" 0603L 6315.31,6752.2 r90 top value=330pF
C46 "GRM188R71H563KA93D" 0603L 6082.52,6662.2 r180 top value=0.056uF
C47 "GRM188R71E105KA12D" 0603L 6335,6352 r90 bottom value=1uF
C48 "GRM188R71E105KA12D" 0603L 6280,6230 r180 top value=1uF
C49 "GRM1885C2A152JA01D" 0603L 6112.52,6752.2 r90 top value=1500pF
C50 "HHXA800ARA390MJA0G" HXA_JA0 1440,3135 r90 top value=39uF
C51 "HHXA800ARA390MJA0G" HXA_JA0 310,2655 r180 top value=39uF
C52 "HHXA800ARA390MJA0G" HXA_JA0 6760,3135 r90 top value=39uF
C53 "HHXA800ARA390MJA0G" HXA_JA0 7815,2655 r0 top value=39uF
C54 "PCR1H181MCL1GS" CR_1000x1270 4335,390 r270 top value=180uF
C55 "PCR1H181MCL1GS" CR_1000x1270 3865,390 r270 top value=180uF
C56 "HHXA800ARA390MJA0G" HXA_JA0 310,2200 r180 top value=39uF
C57 "HHXA800ARA390MJA0G" HXA_JA0 310,1755 r180 top value=39uF
C58 "HHXA800ARA390MJA0G" HXA_JA0 310,1305 r180 top value=39uF
C59 "HHXA800ARA390MJA0G" HXA_JA0 7820,2205 r0 top value=39uF
C60 "HHXA800ARA390MJA0G" HXA_JA0 7820,1755 r0 top value=39uF
C61 "HHXA800ARA390MJA0G" HXA_JA0 7820,1305 r0 top value=39uF
C62 "C5750X7R2A475M230KA" 2220_280 6370,1650 r180 top value=4.7uF
C63 "C5750X7R2A475M230KA" 2220_280 6370,1400 r180 top value=4.7uF
C64 "C5750X7R2A475M230KA" 2220_280 6375,1650 r180 bottom value=4.7uF
C65 "C5750X7R2A475M230KA" 2220_280 1835,1650 r0 top value=4.7uF
C66 "C5750X7R2A475M230KA" 2220_280 1835,1400 r0 top value=4.7uF
C67 "C5750X7R2A475M230KA" 2220_280 1840,1650 r0 bottom value=4.7uF
C68 "C5750X7R2A475M230KA" 2220_280 4905,1885 r0 top value=4.7uF
C69 "C5750X7R2A475M230KA" 2220_280 4905,1645 r0 top value=4.7uF
C70 "C5750X7R2A475M230KA" 2220_280 4905,1885 r0 bottom value=4.7uF
C71 "C5750X7R2A475M230KA" 2220_280 4905,1645 r0 bottom value=4.7uF
C72 "C0603C101J5GACTU" 0603L 2940,3975 r0 top value=100pF
C73 "C0603C101J5GACTU" 0603L 2940,3920 r0 top value=100pF
C74 "C0603C101J5GACTU" 0603L 3258.46,3928.58 r180 top value=100pF
C75 "C0603C101J5GACTU" 0603L 3255,3980 r180 top value=100pF
C76 "Capacitor" 0805_HV 5885,6770 r90 top value=1uF
C77 "Capacitor" 0805_HV 5755,6835 r180 top value=1uF
C78 "Capacitor" 0805_HV 5570,6740 r90 top value=1uF
C79 "Capacitor" 0603L 2765,4290 r270 top value=0.01uF
C80 "GRM188R71C474KA88D" 0603L 2805,3985 r270 top value=0.47uF
C81 "GRM188R71C474KA88D" 0603L 3380,3945 r90 top value=0.47uF
C82 "C0603C101J5GACTU" 0603L 3505,3860 r0 bottom value=100pF
C83 "C0603C101J5GACTU" 0603L 2740,3540 r180 bottom value=100pF
C84 "GRM188R72A104KA35D" 0603L 2260,6280 r90 top value=0.1uF
C85 "Capacitor" 0603L 2715,4290 r270 top value=0.01uF
C87 "C0603C100J5GACTU" 0603 2100,6155 r0 top value=10pF
C89 "C1608X5R1H104K080AA" 0603 2130,6055 r90 top value=0.1uF
C90 "EMK107BBJ106MA-T" 0603 1930,6280 r90 top value=10uF
C91 "GRM188R72A104KA35D" 0603L 1755,6895 r90 bottom value=0.1uF
C93 "GRM188R72A104KA35D" 0603L 1975,6075 r270 bottom value=0.1uF
C94 "GRM188R72A104KA35D" 0603L 2020,6915 r90 bottom value=0.1uF
C95 "GRM188R71C474KA88D" 0603L 4805,3985 r270 top value=0.47uF
C96 "Capacitor" 0603 1820,5820 r180 top value=0.1uF
C97 "Capacitor" 0603 2055,5555 r90 top value=0.1uF
C98 "Capacitor" 0603L 2050,5845 r90 top value=100pF
C99 "Capacitor" 0603 3255,5345 r0 top value=0.1uF
C100 "Capacitor" 0603 3425,5140 r0 top value=0.015uF
C102 "C0603C101J5GACTU" 0603L 1920,5965 r180 top value=100pF
C104 "Capacitor" 0603 2505,5285 r180 top value=0.015uF
C105 "Capacitor" 0603 2805,5285 r0 top value=0.015uF
C106 "Capacitor" 0603 2580,5660 r180 top value=0.1uF
C107 "Capacitor" 0805_HV 2565,5740 r180 top value=10uF
C108 "Capacitor" 0603 2845,5360 r0 top value=0.1uF
C109 "Capacitor" 0805_HV 2855,5445 r0 top value=10uF
C110 "GCM188R71H103KA37D" 0603 2785,5800 r0 top value=0.01uF
C111 "Capacitor" 0603 2600,6205 r180 top value=0.1uF
C112 "Capacitor" 0603 2840,5925 r0 top value=0.1uF
C113 "Capacitor" 0603 2840,6170 r90 top value=10pF
C114 "Capacitor" 0603 3470,6155 r270 top value=10pF
C115 "Capacitor" 0603 3400,6005 r90 top value=0.1uF
C116 "Capacitor" 0603 3295,5885 r0 top value=0.1uF
C117 "Capacitor" 0805_HV 3305,5800 r0 top value=10uF
C118 "Capacitor" 0603 3235,6385 r180 top value=1uF
C119 "Capacitor" 0603 3080,6155 r270 top value=0.1uF
C120 "Capacitor" 0805_HV 3000,6140 r270 top value=10uF
C121 "Capacitor" 0603 3290,5625 r90 top value=10pF
C122 "Capacitor" 1206 3305,6970 r90 bottom value=1uF
C123 "Capacitor" 1206 3060,7010 r0 bottom value=1uF
C124 "Capacitor" 0805_HV 2930,6655 r180 bottom value=10uF
C125 "Capacitor" 1206 2910,6755 r180 bottom value=1uF
C126 "Capacitor" 1206 3200,6805 r0 bottom value=1uF
C127 "Capacitor" 0603 3165,6715 r0 bottom value=0.1uF
C128 "Capacitor" 0603 3695,7035 r0 bottom value=0.1uF
C131 "Capacitor" 0603 4095,6410 r0 top value=0.22uF
C132 "Capacitor" 0603 4095,5780 r0 top value=0.22uF
C133 "Capacitor" 0603 4095,6475 r0 top value=0.1uF
C134 "Capacitor" 0603 4095,6540 r0 top value=1uF
C135 "Capacitor" 0603 4090,5845 r0 top value=0.1uF
C136 "Capacitor" 0603 4090,5910 r0 top value=1uF
C137 "Capacitor" 0603 4565,5880 r270 top value=0.01uF
C138 "Capacitor" 0603 4495,5880 r270 top value=1uF
C139 "Capacitor" 0603 4775,5880 r270 top value=0.01uF
C140 "Capacitor" 0603 4840,5880 r270 top value=0.01uF
C141 "Capacitor" 0603 4690,6330 r90 top value=1uF
C142 "Capacitor" 0603 4200,6515 r90 top value=1500pF
C143 "GRM188R72A392KA01D" 0603 3895,6340 r180 top value=3900pF
C144 "Capacitor" 0603 3695,6390 r180 top value=1500pF
C145 "Capacitor" 0603 4635,5880 r90 top value=1uF
C146 "Capacitor" 0603 4700,5880 r90 top value=0.1uF
C147 "Capacitor" 0603 4460,6220 r270 top value=2700pF
C148 "Capacitor" 0603 4460,6080 r270 top value=2700pF
C149 "Capacitor" 0603 5205,6265 r270 top value=10pF
C150 "Capacitor" 0603 4195,5875 r90 top value=1500pF
C151 "GRM188R72A392KA01D" 0603 3910,5715 r180 top value=3900pF
C152 "GRM1885C1H200JA01D" 0603 5160,6565 r90 top value=20pF
C153 "GRM1885C1H200JA01D" 0603 4735,6570 r90 top value=20pF
C154 "Capacitor" 0603 3705,5775 r180 top value=1500pF
C155 "Capacitor" 0603 4670,5740 r270 top value=1uF
C156 "Capacitor" 0603 4755,6330 r90 top value=1uF
C157 "Capacitor" 0603 5160,5795 r0 top value=1000pF
C158 "Capacitor" 1206_190 4905,5635 r270 top value=100uF
C159 "Capacitor" 1206_190 4810,5635 r270 top value=100uF
C160 "Capacitor" 0603 5325,5700 r90 top value=1uF
C161 "Capacitor" 0603 5025,5570 r0 top value=1uF
C162 "C0603C120J5GACTU" 0603 3880,6360 r90 bottom value=12pF
C163 "06033C104JAT2A" 0603 3625,6330 r270 bottom value=0.1uF
C164 "C0603C120J5GACTU" 0603 4120,6355 r270 bottom value=12pF
C165 "06033C104JAT2A" 0603 3860,5525 r0 top value=0.1uF
C166 "06033C104JAT2A" 0603 4355,5985 r180 top value=0.1uF
C167 "06033C104JAT2A" 0603 3860,6075 r90 top value=0.1uF
C168 "06033C104JAT2A" 0603 3680,5945 r180 top value=0.1uF
C169 "06033C104JAT2A" 0603 3665,6075 r90 top value=0.1uF
C170 "06035A6R8CAT2A" 0603 3445,6135 r0 bottom value=6.8pF
C171 "06035A6R8CAT2A" 0603 3470,6295 r0 bottom value=6.8pF
C172 "GRM188R6YA225KA12D" 0603 3990,6080 r270 top value=2.2uF
C173 "GRM188R71E105KA12D" 0603 4055,6080 r270 top value=1uF
C174 "06033C104JAT2A" 0603 4355,5920 r180 top value=0.1uF
C175 "GRM188R6YA225KA12D" 0603 4375,6605 r90 bottom value=2.2uF
C176 "06033C104JAT2A" 0603 4310,6605 r270 bottom value=0.1uF
C177 "06033C104JAT2A" 0603 4590,6350 r180 bottom value=0.1uF
C178 "06033C104JAT2A" 0603 4590,6285 r180 bottom value=0.1uF
C179 "GRM188R71E105KA12D" 0603 4485,6840 r0 top value=1uF
C180 "GRM188R71E105KA12D" 0603 4375,6725 r90 top value=1uF
C181 "06031C102JAT2A" 0603 4490,6630 r0 top value=1000pF
C182 "GRM188R71E105KA12D" 0603 4200,6810 r180 top value=1uF
C183 "GRM188R71E105KA12D" 0603 4295,6690 r90 top value=1uF
C184 "06031C102JAT2A" 0603 4110,6685 r90 top value=1000pF
C185 "06035A270JAT2A" 0603 4780,6475 r180 bottom value=27pF
C186 "06035A270JAT2A" 0603 4780,6675 r180 bottom value=27pF
C187 "06033C104JAT2A" 0603 4485,6810 r180 bottom value=0.1uF
C188 "Capacitor" 0603 4485,6875 r0 bottom value=1uF
C189 "GRM188R72A104KA35D" 0603L 1925,6425 r180 top value=0.1uF
C190 "C0603C101J5GACTU" 0603L 4940,3975 r0 top value=100pF
C191 "C0603C101J5GACTU" 0603L 4940,3920 r0 top value=100pF
C192 "C1608X7R1H224K080AB" 0603L 4955,3600 r270 bottom value=0.22uF
C193 "C2012X7R1C225K125AB" 0805_HV 5090,3510 r0 bottom value=2.2uF
C194 "GRM188R71E105KA12D" 0603L 4930,3845 r0 top value=1uF
C195 "C1608X7R1H224K080AB" 0603L 5245,3600 r90 bottom value=0.22uF
C196 "C0603C101J5GACTU" 0603L 5135,4155 r90 bottom value=100pF
C197 "06031C103KAT2A" 0603L 5455,3600 r0 bottom value=0.01uF
C198 "GRM188R71C474KA88D" 0603L 5380,3945 r90 top value=0.47uF
C199 "C0603C101J5GACTU" 0603L 5258.47,3928.58 r180 top value=100pF
C200 "C0603C101J5GACTU" 0603L 5255,3980 r180 top value=100pF
C201 "GRM188R71E153KA01D" 0603L 5430,3685 r90 bottom value=0.015uF
C202 "C0603C101J5GACTU" 0603L 5505,3860 r0 bottom value=100pF
C203 "C0603C101J5GACTU" 0603L 4740,3540 r180 bottom value=100pF
C204 "C1608C0G2A102J080AA" 0603L 5505,3660 r0 bottom value=1000pF
C205 "06031C103KAT2A" 0603L 5192.48,4287.52 r270 bottom value=0.01uF
C206 "HHXA800ARA390MJA0G" HXA_JA0 1440,3135 r90 bottom value=39uF
C207 "HHXA800ARA390MJA0G" HXA_JA0 310,2655 r180 bottom value=39uF
C208 "HHXA800ARA390MJA0G" HXA_JA0 310,2205 r180 bottom value=39uF
C209 "HHXA800ARA390MJA0G" HXA_JA0 310,1755 r180 bottom value=39uF
C210 "HHXA800ARA390MJA0G" HXA_JA0 310,1305 r180 bottom value=39uF
C211 "EMVH101GDA101MLH0S" CAPSMT_62_LH0 805,3225 r90 bottom value=100uF
C212 "HHXA800ARA390MJA0G" HXA_JA0 6760,3135 r90 bottom value=39uF
C213 "HHXA800ARA390MJA0G" HXA_JA0 7815,2655 r0 bottom value=39uF
C214 "HHXA800ARA390MJA0G" HXA_JA0 7820,2205 r0 bottom value=39uF
C215 "HHXA800ARA390MJA0G" HXA_JA0 7820,1755 r0 bottom value=39uF
C216 "HHXA800ARA390MJA0G" HXA_JA0 7820,1305 r0 bottom value=39uF
C217 "EMVH101GDA101MLH0S" CAPSMT_62_LH0 7390,3225 r90 bottom value=100uF
C218 "Capacitor" 0603 2930,5130 r0 top value=0.015uF
C221 "GRM188R61A224KA01D" 0603 2345,4665 r180 top value=0.22uF
C222 "GRM188R61A475MAAJ" 0603 2345,4600 r180 top value=4.7uF
C223 "GRM188R61A106ME69D" 0603 2505,4785 r270 top value=10uF
C224 "GRM188R60J226MEA0D" 0603 2165,4795 r90 top value=22uF
C225 "GRM188R61C104KA01D" 0603 2100,4795 r90 top value=0.1uF
C226 "GRM188R60J226MEA0D" 0603 2295,4895 r180 top value=22uF
C227 "GRM188R71E474KA12D" 0603 2295,4960 r180 top value=0.47uF
C228 "GRM188R61A106ME69D" 0603 2180,4990 r270 top value=10uF
C229 "GRM188R61A106ME69D" 0603 2110,4990 r270 top value=10uF
CC "Pogo Pad" PogoPad 3400,5625 r90 top
CS1 "TESTPOINT" TP_25MIL-SMT 2855,4215 r90 top
CS2 "TESTPOINT" TP_25MIL-SMT 2855,4520 r90 top
CV "Pogo Pad" PogoPad 2415,6020 r0 top
D1 "PMEG6010CEH,115" SOD-123F 2950,3395 r0 bottom value=60V
D2 "PMEG6010CEH,115" SOD-123F 3160,3395 r180 bottom value=60V
D3 "DIODE" SOD-523 3150,5785 r180 top value=75V
D4 "PMEG6010CEH,115" SOD-123F 4950,3395 r0 bottom value=60V
D5 "DIODE_SCHOTTKY" SOD-323 3160,5705 r180 top value=30V
D6 "B530C-13-F" SMC 5850,5455 r90 top value=30V
D7 "CDBC5100-G" SMC 6630,5785 r270 top value=100V
D10 "PMEG6010CEH,115" SOD-123F 5180,3395 r180 bottom value=60V
D11 "150060VS75000" WL-SMCW_GREEN 1645,6020 r270 top value=Green
D12 "150060YS75000" WL-SMCW_YELLOW 1915,6970 r180 top value=Yellow
DVDD_3V3 "Pogo Pad" PogoPad 4620,6695 r90 top
FID1 "Fiducial" Fiducial10-20 750,6830 r0 top
FID2 "Fiducial" Fiducial10-20 610,120 r0 top
FID3 "Fiducial" Fiducial10-20 7600,215 r0 top
FID4 "Fiducial" Fiducial10-20 750,6830 r180 bottom
FID5 "Fiducial" Fiducial10-20 750,245 r180 bottom
FID6 "Fiducial" Fiducial10-20 7600,215 r180 bottom
H1 "NY PMS 440 0025 PH" "NY PMS 440 0025 PH" 250,6800 r0 top locked
H2 "NY PMS 440 0025 PH" "NY PMS 440 0025 PH" 8050,6750 r0 top locked
H3 "NY PMS 440 0025 PH" "NY PMS 440 0025 PH" 250,245 r0 top locked
H4 "NY PMS 440 0025 PH" "NY PMS 440 0025 PH" 8050,245 r0 top
H5 "2205" KEYSTONE_2205 250,6800 r180 bottom locked
H6 "2205" KEYSTONE_2205 8050,6750 r180 bottom locked
H7 "2205" KEYSTONE_2205 250,245 r180 bottom locked
H8 "2205" KEYSTONE_2205 8050,245 r180 bottom locked
H9 "NY PMS 440 0025 PH" "NY PMS 440 0025 PH" 280,3885 r0 top
H10 "NY PMS 440 0025 PH" "NY PMS 440 0025 PH" 8040,3885 r0 top
H11 "2205" KEYSTONE_2205 275,3960 r180 bottom
H12 "2205" KEYSTONE_2205 8040,3885 r180 bottom
IBAT "Pogo Pad" PogoPad 2775,6380 r90 top
J1 "HTSW-103-07-G-S" Samtec_HTSW-103-07-G-S 3940,3920 r180 top
J2 "PEC10DAAN" SULLINS_PEC10DAAN 4250,5370 r90 top
J3 "HTSW-102-07-G-S" Samtec_HTSW-102-07-G-S 3040,4470 r0 top
J4 "HTSW-102-07-G-S" Samtec_HTSW-102-07-G-S 5700,5150 r180 top
J5 "HTSW-103-07-G-S" Samtec_HTSW-103-07-G-S 3295,4680 r180 top
J6 "Header_3x1" Samtec_HTSW-103-07-G-S 5005,5305 r90 top
J7 "Header_3x1" Samtec_HTSW-103-07-G-S 5125,5305 r90 top
J8 "Header_3x1" Samtec_HTSW-103-07-G-S 5245,5305 r90 top
J9 "108-0740-001" Johnson_108-0740-001 2350,480 r90 top
J10 "108-0740-001" Johnson_108-0740-001 5125,480 r270 top
J11 "108-0740-001" Johnson_108-0740-001 3100,480 r90 top
J12 "108-0740-001" Johnson_108-0740-001 5875,480 r270 top
J13 "HTSW-103-07-G-S" Samtec_HTSW-103-07-G-S 5940,3920 r180 top
J14 "HTSW-102-07-G-S" Samtec_HTSW-102-07-G-S 2975,5940 r270 top
J16 "HTSW-102-07-G-S" Samtec_HTSW-102-07-G-S 5465,6750 r270 top
J17 "Header_5x2" Assman_AWHW-10G-0x02-T 3665,6905 r270 top
J18 "802-10-008-10-001000" Mill-Max_802-10-008-10-001000 2600,6950 r0 top
J19 "PRPC008DAAN-RC" Sullins_xxxC008DAAN 4995,6955 r90 top
J20 "10118193-0001LF" FCI_10118193-0001LF 4330,7090 r180 top
J22 "TSW-107-07-G-S" TSW-107-07-G-S 5960,7000 r0 top
J23 "HTSW-103-07-G-S" Samtec_HTSW-103-07-G-S 6520,7000 r180 top
J25 "Header_3x1" Samtec_HTSW-103-07-G-S 6115,4575 r90 top
J26 "Header_3x1" Samtec_HTSW-103-07-G-S 6235,4575 r90 top
J27 "HTSW-102-07-G-S" Samtec_HTSW-102-07-G-S 5040,4470 r0 top
J28 "PEC10DAAN" SULLINS_PEC10DAAN 5240,4740 r90 top
J29 "HTSW-103-07-G-S" Samtec_HTSW-103-07-G-S 4285,4315 r180 top
J30 "HTSW-103-07-G-S" Samtec_HTSW-103-07-G-S 1500,6300 r270 top
J35 "HTSW-102-07-G-S" Samtec_HTSW-102-07-G-S 1925,5325 r270 top
J37 "HTSW-102-07-G-S" Samtec_HTSW-102-07-G-S 1765,5325 r270 top
L1 "74436410470" WE-HCF_2818 2640,2950 r90 top value=4.7uH
L2 "74436410470" WE-HCF_2818 5550,2950 r90 top value=4.7uH
L3 "MSS1278-473MLB" mss1278 6220,5910 r180 top value=47uH
L4 "Ferrite_Bead" 0603 3345,6790 r90 bottom value="600 ohm"
L5 "74436410470" WE-HCF_2818 2640,2950 r90 bottom value=4.7uH
L6 "74436410470" WE-HCF_2818 5550,2950 r90 bottom value=4.7uH
L7 "MPZ2012S601A" 0805_HV 2590,4800 r270 top value="600 ohm"
L8 "MPZ2012S601A" 0805_HV 2220,5105 r0 top value="600 ohm"
LBL1 "=Note" Label_1250x250 1120,4255 r0 top
Logo2 "Pb-Free Symbol" Pb-Free_Overlay_Medium 1550,5205 r90 top
Logo3 "FCC disclaimer" FCC_disclaimer_stacked 1335,5520 r90 top
LOGO4 "CAUTION HOT SURFACE" IEC_HotSurface_Small 5995,2390 r0 top
LOGO5 "CAUTION HOT SURFACE" IEC_HotSurface_Small 2230,2335 r0 top
LOGO6 "DANGER HIGH VOLTAGE" IEC_HighVoltage_Small 1510,505 r0 top
LOGO7 "CAUTION HOT SURFACE" IEC_HotSurface_Small 3125,2360 r0 top
LOGO8 "CAUTION HOT SURFACE" IEC_HotSurface_Small 5100,2385 r0 top
NT1 "Net-Tie" Net-Tie_10mil 3110,3710 r270 bottom net-tie
NT2 "Net-Tie" Net-Tie_10mil 6282.2,6521.37 r270 top net-tie
NT3 "Net-Tie" Net-Tie_10mil 5110,3710 r270 bottom net-tie
Q1 "TK65G10N1,RQ" DDPAK 1675,2030 r180 top
Q2 "TK65G10N1,RQ" DDPAK 2310,1860 r90 top
Q3 "TK65G10N1,RQ" DDPAK 2805,1860 r90 top
Q4 "TK65G10N1,RQ" DDPAK 1675,2530 r180 top
Q5 "TK65G10N1,RQ" DDPAK 1675,2030 r180 bottom
Q6 "TK65G10N1,RQ" DDPAK 2310,1860 r90 bottom
Q8 "TK65G10N1,RQ" DDPAK 2805,1860 r90 bottom
Q9 "TK65G10N1,RQ" DDPAK 1675,2530 r180 bottom
Q10 "TK65G10N1,RQ" DDPAK 6520,2030 r0 top
Q11 "TK65G10N1,RQ" DDPAK 5915,1860 r90 top
Q12 "TK65G10N1,RQ" DDPAK 5415,1860 r90 top
Q13 "TK65G10N1,RQ" DDPAK 6520,2530 r0 top
Q14 "SI7454DDP-T1-GE3" PowerPAK_SO-8 6920,5745 r270 top value=100V
Q15 "SI7454DDP-T1-GE3" PowerPAK_SO-8 6140,5525 r180 top value=100V
Q16 "2N7002E-T1-E3" SOT-23 1850,6055 r90 bottom value=60V
Q17 "2N7002E-T1-E3" SOT-23 1755,6050 r180 top value=60V
Q18 "2N7002E-T1-E3" SOT-23 1915,6860 r90 top value=60V
Q19 "TK65G10N1,RQ" DDPAK 6520,2030 r0 bottom
Q20 "TK65G10N1,RQ" DDPAK 5915,1860 r90 bottom
Q21 "TK65G10N1,RQ" DDPAK 5415,1860 r90 bottom
Q22 "TK65G10N1,RQ" DDPAK 6520,2530 r0 bottom
R1 "CRCW060395K3FKEA" 0603L 2745,3750 r0 bottom value=95.3k
R2 "CRCW0603634RFKEA" 0603L 2695,3650 r180 bottom value=634
R3 "CRCW06039K09FKEA" 0603L 2650,4285 r270 bottom value=9.09k
R4 "CRCW0603100KFKEA" 0603 3910,3765 r0 top value=100k
R5 "CRCW060395K3FKEA" 0603L 3410,3915 r0 bottom value=95.3k
R6 "ERJ-3EKF4992V" 0603 3520,3760 r180 bottom value=49.9k
R7 "CRCW060310K0FKEA" 0603L 2985,4275 r270 bottom value=10.0k
R8 "CRCW060395K3FKEA" 0603L 4745,3750 r0 bottom value=95.3k
R9 "CRCW06039K09FKEA" 0603L 4650,4285 r270 bottom value=9.09k
R10 "ERJ-3EKF1001V" 0603 5905,6660 r180 top value=1.00k
R11 "CRCW060310K0FKEA" 0603L 3255,4148.33 r270 bottom value=10.0k
R12 "CRCW060349K9FKEA" 0603L 3195,4530 r270 top value=49.9k
R13 "CRCW060340K2FKEA" 0603L 3205,4150 r270 bottom value=40.2k
R14 "CRCW080524R9FKEA" 0805L 2700,3840 r180 top value=24.9
R15 "ERJ-3EKF4022V" 0603 2745,3820 r0 bottom value=40.2k
R16 "WSLP2726L5000FEA" FP-WSLP2726L5000FEA_2726-MFG 4125,2090 r270 top
R17 "CRCW060351K1FKEA" 0603L 3505,3810 r180 bottom value=51.1k
R18 "CRCW060354K9FKEA" 0603L 2740,3595 r0 bottom value=54.9k
R19 "CRCW0603634RFKEA" 0603L 3505,3710 r180 bottom value=634
R20 "CRCW06039K09FKEA" 0603L 3240,4287.52 r90 bottom value=9.09k
R21 "WSL27261L000FEB" RES_WSL2726 3430,2530 r0 top value=0.001
R22 "CRCW080549K9FKEA" 0805_HV 2035,1970 r270 top value=49.9k
R23 "CRCW0603634RFKEA" 0603L 4695,3650 r180 bottom value=634
R24 "CRCW080549K9FKEA" 0805_HV 2240,1455 r0 top value=49.9k
R25 "CRCW080549K9FKEA" 0805_HV 2745,1455 r0 top value=49.9k
R26 "CRCW08051R00FKEA" 0805_HV 2000,1830 r0 top value=1.00
R27 "CRCW08051R00FKEA" 0805_HV 2090,1490 r270 top value=1.00
R28 "CRCW08051R00FKEA" 0805_HV 2595,1490 r270 top value=1.00
R29 "CRCW080549K9FKEA" 0805_HV 2055,2475 r270 top value=49.9k
R30 "CRCW08051R00FKEA" 0805_HV 2020,2335 r0 top value=1.00
R31 "CRCW06031R00JNEA" 0603L 2570,4260 r0 top value=1.0
R32 "WSL27261L000FEB" RES_WSL2726 4760,2540 r0 top value=0.001
R33 "CRCW080549K9FKEA" 0805_HV 6185,2250 r270 top value=49.9k
R34 "CRCW0603100KFKEA" 0603 5910,3765 r0 top value=100k
R35 "CRCW080549K9FKEA" 0805_HV 5855,1455 r0 top value=49.9k
R36 "CRCW080549K9FKEA" 0805_HV 5360,1455 r0 top value=49.9k
R37 "CRCW08051R00FKEA" 0805_HV 6315,2285 r180 top value=1.00
R38 "CRCW08051R00FKEA" 0805_HV 5705,1490 r270 top value=1.00
R39 "CRCW08051R00FKEA" 0805_HV 5210,1490 r270 top value=1.00
R40 "CRCW080549K9FKEA" 0805_HV 6185,2740 r270 top value=49.9k
R41 "CRCW08051R00FKEA" 0805_HV 6315,2780 r180 top value=1.00
R42 "CRCW06031R00JNEA" 0603L 2570,4485 r0 top value=1.0
R43 "CRCW060395K3FKEA" 0603L 5410,3915 r0 bottom value=95.3k
R44 "Resistor" 0603 4539.93,3755 r90 bottom value=0
R45 "RC0603FR-074K7L" 0603 5390,3760 r0 bottom value=4.70k
R46 "CRCW060318K2FKEA" 0603L 6378.11,6752.2 r270 top value=18.2k
R47 "PRL1632-R068-F-T1" 0612 6635,5525 r90 top value=0.068
R48 "RC0603FR-0724KL" 0603L 6052.52,6752.2 r270 top value=24.0k
R49 "RC0603FR-077K32L" 0603 6180,6765 r270 top value=7.32k
R50 "RC0603FR-0752K3L" 0603 6035,6605 r180 top value=52.3k
R51 "CRCW060310R0FKEA" 0603L 6025,6545 r0 top value=10.0
R52 "RC0603FR-0710R5L" 0603 1955,5820 r180 top value=10.5
R53 "CRCW060320K0FKEA" 0603L 6430,6815 r270 top value=20.0k
R54 "CRCW08052R00JNEA" 0805_HV 2925,3500 r180 bottom value=2.0
R55 "CRCW08052R00JNEA" 0805_HV 3255,3500 r180 bottom value=2.0
R56 "CRCW06031R00JNEA" 0603L 2735,4010 r180 top value=1.0
R57 "CRCW06031R00JNEA" 0603L 2735,3955 r180 top value=1.0
R58 "CRCW06031R00JNEA" 0603L 3470,3970 r0 top value=1.0
R59 "CRCW06031R00JNEA" 0603L 3470,3920 r0 top value=1.0
R60 "RC0603FR-074K7L" 0603 3390,3760 r0 bottom value=4.70k
R61 "Resistor" 0603L 2740,4215 r0 top value=10.0k
R62 "Resistor" 0603L 3685,5175 r0 top value=10.0k
R63 "Resistor" 0603L 2570,4310 r0 top value=10.0k
R64 "Resistor" 0603L 3580,5175 r0 top value=10.0k
R65 "Resistor" 0603 3425,5210 r0 top value=499
R67 "Resistor" 0603 3095,5045 r0 top value=0
R68 "Resistor" 0603 2620,5250 r270 top value=499
R69 "Resistor" 0603 2695,5250 r270 top value=499
R70 "1.15k" 0603 2465,5490 r180 top
R71 "Resistor" 0603 2680,5765 r270 top value=499
R72 "Resistor" 0603 2740,6205 r0 top value=0
R73 "RC0603FR-0710R5L" 0603 2805,6290 r180 top value=10.5
R74 "Resistor" 0603 3015,6285 r0 top value=10.0k
R76 "CRCW06034K42FKEA" 0603L 2000,6045 r90 top value=4.42k
R78 "CRCW060326K7FKEA" 0603L 1920,6070 r0 top value=26.7k
R80 "CRCW06031K00FKEA" 0603 2060,6055 r90 top value=1.00k
R81 "CRCW060310K0FKEA" 0603L 2395,6430 r180 top value=10.0k
R82 "Resistor" 0603 3400,6155 r270 top value=1.00k
R84 "MCT06030C1004FP500" 0603 1770,6245 r180 top value=1.00Meg
R86 "CRCW060310K0FKEA" 0603L 2395,6480 r180 top value=10.0k
R87 "ERJ-3EKF4992V" 0603 5505,3760 r180 bottom value=49.9k
R89 "CRCW060310K0FKEA" 0603L 4985,4275 r270 bottom value=10.0k
R90 "CRCW06034K99FKEA" 0603L 1645,5910 r90 top value=4.99k
R91 "CRCW06034K99FKEA" 0603L 1785,6970 r0 top value=4.99k
R92 "ERJ-3EKF1002V" 0603 4735.07,3915 r270 bottom value=10.0k
R93 "Resistor" 0603 3235,6320 r180 top value=10.0k
R94 "ERJ-3EKF1002V" 0603 4799.93,3915 r90 bottom value=10.0k
R95 "CRCW08052R00JNEA" 0805_HV 4925,3500 r180 bottom value=2.0
R96 "Resistor" 0603 2975,6880 r270 bottom value=0.51
R99 "Resistor" 0603 3565,7035 r180 bottom value=10k
R101 "CRCW060320K0FKEA" 0603L 1920,6020 r0 top value=20.0k
R102 "CRCW060310K0FKEA" 0603L 3080,4200 r0 top value=10.0k
R111 "RC0603FR-071K5L" 0603 4235,6410 r0 top value=1.50k
R112 "RC0603FR-071K5L" 0603 4030,6340 r180 top value=1.50k
R113 "Resistor" 0603 4265,6515 r270 top value=49.9
R114 "RC0603FR-071K5L" 0603 3795,6305 r90 top value=1.50k
R115 "Resistor" 0603 3595,6355 r270 top value=49.9
R116 "Resistor" 0603 3690,6460 r180 top value=100k
R117 "RC0603FR-071K5L" 0603 3695,6325 r180 top value=1.50k
R118 "Resistor" 0603 4355,6255 r0 top value=100
R119 "Resistor" 0603 4355,6190 r0 top value=100
R120 "Resistor" 0603 4625,6330 r90 top value=499
R121 "Resistor" 0603 5135,6265 r90 top value=100k
R122 "Resistor" 0603 4550,6985 r90 top value=100k
R123 "Resistor" 0603 5180,6800 r0 bottom value=100k
R124 "RC0603FR-071K5L" 0603 4230,5780 r0 top value=1.50k
R125 "Resistor" 0603 4355,6115 r0 top value=100
R126 "RC0603FR-073K3L" 0603 4040,5715 r180 top value=3.30k
R127 "Resistor" 0603 4355,6045 r0 top value=100
R128 "Resistor" 0603 4260,5875 r270 top value=49.9
R129 "RC0603FR-073K3L" 0603 3810,5680 r90 top value=3.30k
R130 "Resistor" 0603 3600,5745 r270 top value=49.9
R131 "Resistor" 0603 3705,5840 r180 top value=100k
R132 "RC0603FR-071K5L" 0603 3705,5715 r180 top value=1.50k
R133 "Resistor" 0603 4735,5740 r90 top value=0
R134 "Resistor" 0603 4990,5670 r90 top value=1.00
R135 "Resistor" 0603 4960,6425 r0 top value=0
R136 "Resistor" 0603 4765,6425 r0 top value=0
R137 "Resistor" 0603 4855,6315 r0 top value=1.00Meg
R138 "Resistor" 0603 4980,6800 r180 bottom value=1.00k
R139 "CRCW060310K0FKEA" 0603 3730,6075 r270 top value=10.0k
R140 "CRCW06031M00FKEA" 0603 3585,6115 r270 top value=1.00Meg
R141 "CRCW0603100RFKEA" 0603 3795,6075 r90 top value=100
R142 "CRCW06030000Z0EA" 0603 4015,5525 r180 top value=0
R143 "CRCW06034K87FKEA" 0603 3445,6070 r180 bottom value=4.87k
R144 "CRCW060310K0FKEA" 0603L 5080,4200 r0 top value=10.0k
R145 "CRCW06032K00FKEA" 0603 4150,6485 r0 bottom value=2.00k
R146 "CRCW060351R0JNEA" 0603 3690,6330 r270 bottom value=51
R147 "Resistor" 0603 4980,6735 r0 top value=0
R148 "CRCW060310K0FKEA" 0603L 5255,4148.33 r270 bottom value=10.0k
R149 "CRCW06031K00FKEA" 0603 4440,6605 r90 bottom value=1.00k
R150 "CRCW06031M00FKEA" 0603 4750,6575 r270 bottom value=1.00Meg
R151 "CRCW060310K0FKEA" 0603 4320,5955 r90 bottom value=10.0k
R152 "CRCW060310K0FKEA" 0603 4385,5955 r90 bottom value=10.0k
R153 "CRCW06038K06FKEA" 0603 4505,6605 r270 bottom value=8.06k
R154 "CRCW060310K0FKEA" 0603 4590,6435 r180 bottom value=10.0k
R155 "ERJ-3EKF1002V" 0603 2800,3915 r90 bottom value=10.0k
R156 "ERJ-3EKF1002V" 0603 2735,3915 r270 bottom value=10.0k
R157 "CRCW060349K9FKEA" 0603L 4185,4145 r270 top value=49.9k
R158 "CRCW060340K2FKEA" 0603L 5205,4150 r270 bottom value=40.2k
R159 "CRCW080524R9FKEA" 0805L 4700,3840 r180 top value=24.9
R160 "Resistor" 0603 3700,3695 r90 bottom value=0
R161 "Resistor" 0603 2540,3755 r90 bottom value=0
R162 "RT0603DRE072KL" 0603 3155,5885 r180 top value=2.00k
R163 "Resistor" 0603 2305,5990 r270 top value=0
R164 "Resistor" 0603 5505,6450 r90 top value=0
R165 "Resistor" 0603 5505,6215 r90 top value=0
R166 "CRCW08052R00JNEA" 0805_HV 5255,3500 r180 bottom value=2.0
R167 "ERJ-3EKF4022V" 0603 4745,3820 r0 bottom value=40.2k
R168 "Resistor" 0603 5699.93,3695 r90 bottom value=0
R169 "CRCW060351K1FKEA" 0603L 5505,3810 r180 bottom value=51.1k
R170 "CRCW060354K9FKEA" 0603L 4740,3595 r0 bottom value=54.9k
R171 "CRCW06039K09FKEA" 0603L 5240,4287.52 r90 bottom value=9.09k
R172 "CRCW0603634RFKEA" 0603L 5505,3710 r180 bottom value=634
R173 "WSL27261L000FEB" RES_WSL2726 3430,2530 r0 bottom value=0.001
R174 "CRCW080549K9FKEA" 0805_HV 2010,2230 r270 bottom value=49.9k
R175 "CRCW080549K9FKEA" 0805_HV 2360,1475 r180 bottom value=49.9k
R176 "CRCW080549K9FKEA" 0805_HV 2865,1475 r180 bottom value=49.9k
R177 "CRCW06031R00JNEA" 0603L 4735,4010 r180 top value=1.0
R178 "CRCW06031R00JNEA" 0603L 4735,3955 r180 top value=1.0
R179 "CRCW08051R00FKEA" 0805_HV 1885,2265 r0 bottom value=1.00
R180 "CRCW08051R00FKEA" 0805_HV 2510,1510 r270 bottom value=1.00
R181 "CRCW08051R00FKEA" 0805_HV 3015,1510 r270 bottom value=1.00
R182 "CRCW080549K9FKEA" 0805_HV 2010,2735 r270 bottom value=49.9k
R183 "CRCW08051R00FKEA" 0805_HV 1885,2770 r0 bottom value=1.00
R184 "WSL27261L000FEB" RES_WSL2726 4760,2530 r0 bottom value=0.001
R185 "CRCW080549K9FKEA" 0805_HV 6165,1895 r90 bottom value=49.9k
R186 "CRCW06031R00JNEA" 0603L 5470,3970 r0 top value=1.0
R187 "CRCW06031R00JNEA" 0603L 5470,3920 r0 top value=1.0
R188 "CRCW080549K9FKEA" 0805_HV 5975,1475 r180 bottom value=49.9k
R189 "CRCW080549K9FKEA" 0805_HV 5475,1475 r180 bottom value=49.9k
R190 "CRCW08051R00FKEA" 0805_HV 6315,1850 r180 bottom value=1.00
R191 "CRCW08051R00FKEA" 0805_HV 6125,1510 r270 bottom value=1.00
R192 "CRCW08051R00FKEA" 0805_HV 5625,1510 r270 bottom value=1.00
R193 "CRCW080549K9FKEA" 0805_HV 6185,2290 r270 bottom value=49.9k
R194 "CRCW08051R00FKEA" 0805_HV 6315,2285 r180 bottom value=1.00
R195 "Resistor" 0603 2930,5195 r180 top value=499
R200 "RG1608P-4871-B-T5" 0603 2465,5425 r180 top value=4.87k
R201 "RT0603DRE074R7L" 0603 2295,5025 r180 top value=4.70
S1 "Switch_PushButton" SW_TL1015AF160QG#1 5315,6300 r90 top
S2 "TL1015AF160QG" SW_TL1015AF160QG#2 3475,6440 r270 top
S3 "SW DPDT" SOT23-6_N 2200,5375 r180 top
T1 "CXS70-14-C" Panduit_CXS70-14-C 2350,480 r90 top
T2 "CXS70-14-C" Panduit_CXS70-14-C 5125,480 r90 top
T3 "CXS70-14-C" Panduit_CXS70-14-C 3100,480 r90 top
T4 "CXS70-14-C" Panduit_CXS70-14-C 5875,480 r90 top
U1 "LM5170QPHPRQ1" PHP0048D_L 3100,3840 r180 bottom
U2 "LM6142AIM/NOPB" D0008A_N 2100,6355 r270 top
U3 "TPS70950DBVR" DBV0005A_N 5730,6460 r180 top
U4 "TPS70950DBVR" DBV0005A_N 5730,6220 r180 top
U5 "LM5118MH/NOPB" MXA20A_N 6295,6455 r270 top
U6 "LM5170QPHPRQ1" PHP0048D_L 5100,3840 r180 bottom
U7 "PM-CHP-LM2664M6-6" DBV0006A_M 5735,6700 r0 top
U8 "OPA827AIDR" D0008A_L 1900,5625 r90 top
U9 "SN74LV4053ATPWRQ1" PW0016A_L 3175,5195 r0 top
U10 "SN74LVC1G04QDBVRQ1" DBV0005A_N 2135,6895 r180 bottom
U11 "SN74LV1T00DBVR" DBV0005A_N 2090,6045 r180 bottom
U12 "SN74LV1T32DBVR" DBV0005A_N 1875,6870 r180 bottom
U13 "INA828ID" D0008A_N 2655,5470 r90 top
U14 "OPA827AIDR" D0008A_L 2655,6030 r90 top
U15 "TLV07IDR" D0008A_N 3235,6080 r270 top
U16 "TI-REF5050D8" D0008A_N 3060,6940 r180 top
U17 "DACx0004DMD" DMD0014A 3115,6565 r270 top
U19 "THS4561IDGKR" DGK0008A_N 3895,6455 r180 top
U20 "THS4561IDGKR" DGK0008A_N 3900,5835 r180 top
U21 "ADS131A04IPBSR" PBS0032A_L 4705,6105 r0 top
U22 "TI-REF5025DGK8" DGK0008A_N 5155,5680 r180 top
U23 "TM4C1294NCPDTI3R" PDT0128A 3885,5900 r90 bottom
U24 "TPS73733DRVR" DRV0006A 4475,6730 r90 top
U25 "TPS71718DCKR" DCK0005A_N 4200,6700 r270 top
U26 "TPD4S012DRYR" DRY0006A 4325,6835 r270 top
U27 "USB3320C-EZK" Microchip_32QFN-3304-5x5B 4380,6400 r90 bottom
U28 "24AA256-I/ST" TSSOP-8 4380,5690 r90 bottom
U29 "LM7705MM/NOPB" MUA08A_N 2345,4780 r180 top
V1.8 "Pogo Pad" PogoPad 4375,6575 r90 top
V-5 "Pogo Pad" PogoPad 5350,6700 r0 top
VBAT "Pogo Pad" PogoPad 2060,5735 r90 top locked
VREF_ADC "Pogo Pad" PogoPad 4990,5830 r90 top
VREF_DAC "Pogo Pad" PogoPad 3055,6790 r90 top
VREF_LV "Pogo Pad" PogoPad 1750,6340 r90 top
Y1 "XTAL_4P_13_G24" CTS_407 4945,6580 r270 top
Y2 "ABM3-25.000MHZ-D2Y-T" XTAL_ABM3 4000,6405 r270 bottom
Y3 "SSPT7F-7PF20-R" Seiko_SSP-T 3410,6215 r90 bottom
Y4 "ABM3-24.000MHZ-D2Y-T" XTAL_ABM3 4625,6590 r270 bottom
ZZ1 "This Assembly Note is for PCB labels only" AssemblyNoteLabel -1245,8050 r0 top
ZZ2 "These assemblies are ESD sensitive, ESD precautions shall be observed." AssemblyNote -1245,7950 r0 top
ZZ3 "These assemblies must be clean and free from flux and all contaminants. Use of no clean flux is not acceptable." AssemblyNote -1245,7850 r0 top
ZZ4 "These assemblies must comply with workmanship standards IPC-A-610 Class 2, unless otherwise specified." AssemblyNote -1245,7750 r0 top

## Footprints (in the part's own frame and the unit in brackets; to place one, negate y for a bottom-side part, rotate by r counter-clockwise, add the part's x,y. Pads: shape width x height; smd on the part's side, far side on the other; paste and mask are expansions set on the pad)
0603 [mm] "0603 from SM-752 data"
  rect 1x0.95 smd: 1(-0.8,0) 2(0.8,0)
  silkscreen extent -1.52,-0.69 1.52,0.69, body extent -0.87,-0.47 0.87,0.47, height 1
0603L [mm] "0603 from SM-752 data"
  rect 0.8x0.85 smd: 1(-0.7,0) 2(0.7,0)
  silkscreen extent -0.07,-0.33 0.07,0.33, body extent -0.87,-0.47 0.87,0.47, height 1
0612 [mm] "Panasonic recommended land pattern, fb97d03ed01.pdf dated April 2008"
  rect 0.65x2.75 smd: 1(-0.775,0) 2(0.775,0)
  silkscreen extent -1.1,-1.9 1.1,1.9, body extent -0.9,-1.7 0.9,1.7, height 0.85
0805_HV [mil] "0805 with 30mil clearance between pads"
  rect 50x63 smd: 1(-40,0) 2(40,0)
  silkscreen extent -74,-40 74,40, body extent -43,-29 43,29, height 57
0805L [mm] "0805 from SM-752 data"
  rect 1.1x1.4 smd: 1(-0.75,0) 2(0.75,0)
  body extent -1.1,-0.72 1.1,0.72, height 1.45
1206 [mm] "1206 from SM-752 data"
  rect 1.3x1.85 smd: 1(-1.45,0) 2(1.45,0)
  silkscreen extent -2.4,-1.21 2.4,1.21, body extent -1.7,-0.9 1.7,0.9, height 1.35
1206_190 [mm] "1206_190"
  rect 1.1x1.6 smd: 1(-1.7,0) 2(1.7,0)
  silkscreen extent -0.9,-1 0.9,1, body extent -1.75,-0.95 1.75,0.95, height 1.9
2220_250 [mm] "2220"
  rect 1.6x5.3 smd: 1(-2.6,0) 2(2.6,0)
  silkscreen extent -3.69,-2.94 3.69,2.94, body extent -2.95,-2.62 2.95,2.62, height 2.5
2220_280 [mm] "Chip Capacitor, Body 5.7x5.0mm, IPC Medium Density"
  rect 1.6x5.3 smd: 1(-2.6,0) 2(2.6,0)
  silkscreen extent -3.69,-2.94 3.69,2.94, body extent -2.95,-2.62 2.95,2.62, height 2.8
AssemblyNote [mil] "Assembly Note"
AssemblyNoteLabel [mil] "Assembly Note for PCB Labels"
Assman_AWHW-10G-0x02-T [mm] "Header, 2.54mm, 5x2, TH"
  rect 1.55x1.55 hole 1.02: 1(-1.27,5.08)
  round 1.55 hole 1.02: 2(1.27,5.08) 3(-1.27,2.54) 4(1.27,2.54) 5(-1.27,0) 6(1.27,0) 7(-1.27,-2.54) 8(1.27,-2.54) 9(-1.27,-5.08) 10(1.27,-5.08)
  silkscreen extent -4.9,-10.31 4.47,10.31, body extent -4.47,-10.31 4.47,10.31, height 9.15
CAPSMT_62_HC0 [mm] "8 x 12mm:  Chemi-Con HC0"
  rect 4.2x2.2 smd: 1(-3.638,0.012) 2(3.662,0.012)
  silkscreen extent -4.24,-4.24 4.26,4.26, body extent -4.24,-4.24 4.26,4.26, height 12.5
CAPSMT_62_JA0 [mm] "10 x 10mm:  Chemi-Con JA0"
  rect 4.4x2.2 smd: 1(-4.45,0) 2(4.45,0)
  silkscreen extent -5.25,-5.25 5.25,5.25, body extent -5.25,-5.25 5.25,5.25, height 10.5
CAPSMT_62_LH0 [mm] "16 x 16.5mm:  Chemi-Con LH0"
  rect 7.8x9.6 smd: 1(-6.25,0) 2(6.25,0)
  silkscreen extent -8.55,-8.55 8.55,8.55, body extent -8.55,-8.55 8.55,8.55, height 17
CR_1000x1270 [mm] "SMD, 2-Leads, Dia 10.5mm, Pin Spacing 8mm"
  rect 4x2 smd: 1(-4,0) 2(4,0)
  silkscreen extent -7.4,-5.25 5.25,5.25, body extent -5.25,-5.25 5.25,5.25, height 12.71
CTS_407 [mm] "SMD, 4-Leads, Body 7.2x5.2mm"
  rect 1.4x2.2 smd: 1(-1.27,3.2) 2(-1.27,-3.2) 3(1.27,-3.2) 4(1.27,3.2)
  silkscreen extent -2.65,-3.6 2.6,4.15, body extent -2.6,-3.6 2.6,3.6, height 1.3
D0008A_L [mm] "SOIC, 8-Leads, Body 4.9x3.9mm, Pitch 1.27mm, IPC High Density"
  oval 1.25x0.55 smd: 1(-2.625,1.905) 2(-2.625,0.635) 3(-2.625,-0.635) 4(-2.625,-1.905) 5(2.625,-1.905) 6(2.625,-0.635) 7(2.625,0.635) 8(2.625,1.905)
  silkscreen extent -3.1,-2.5 0.9,2.5, body extent -3,-2.45 3,2.45, height 1.63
